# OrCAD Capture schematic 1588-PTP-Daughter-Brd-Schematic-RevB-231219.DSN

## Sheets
1 01_TITLE_BLOCK: title: 01_Title_Block; rev: v2.1
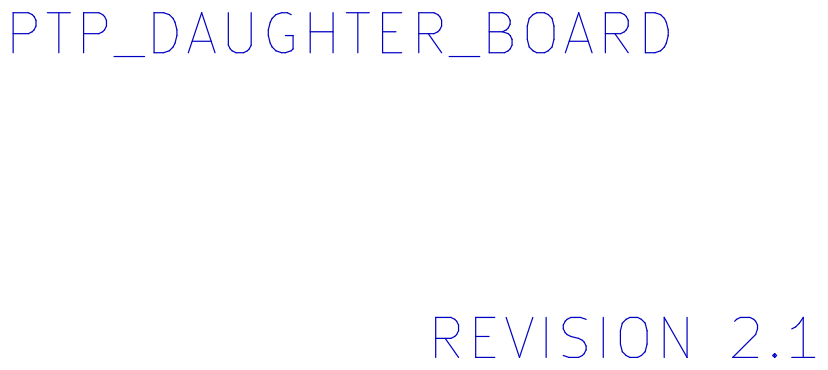
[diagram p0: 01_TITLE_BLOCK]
2 10_FMC_CONNECTOR_2: size A3; title: 10_FMC_CONNECTOR_2
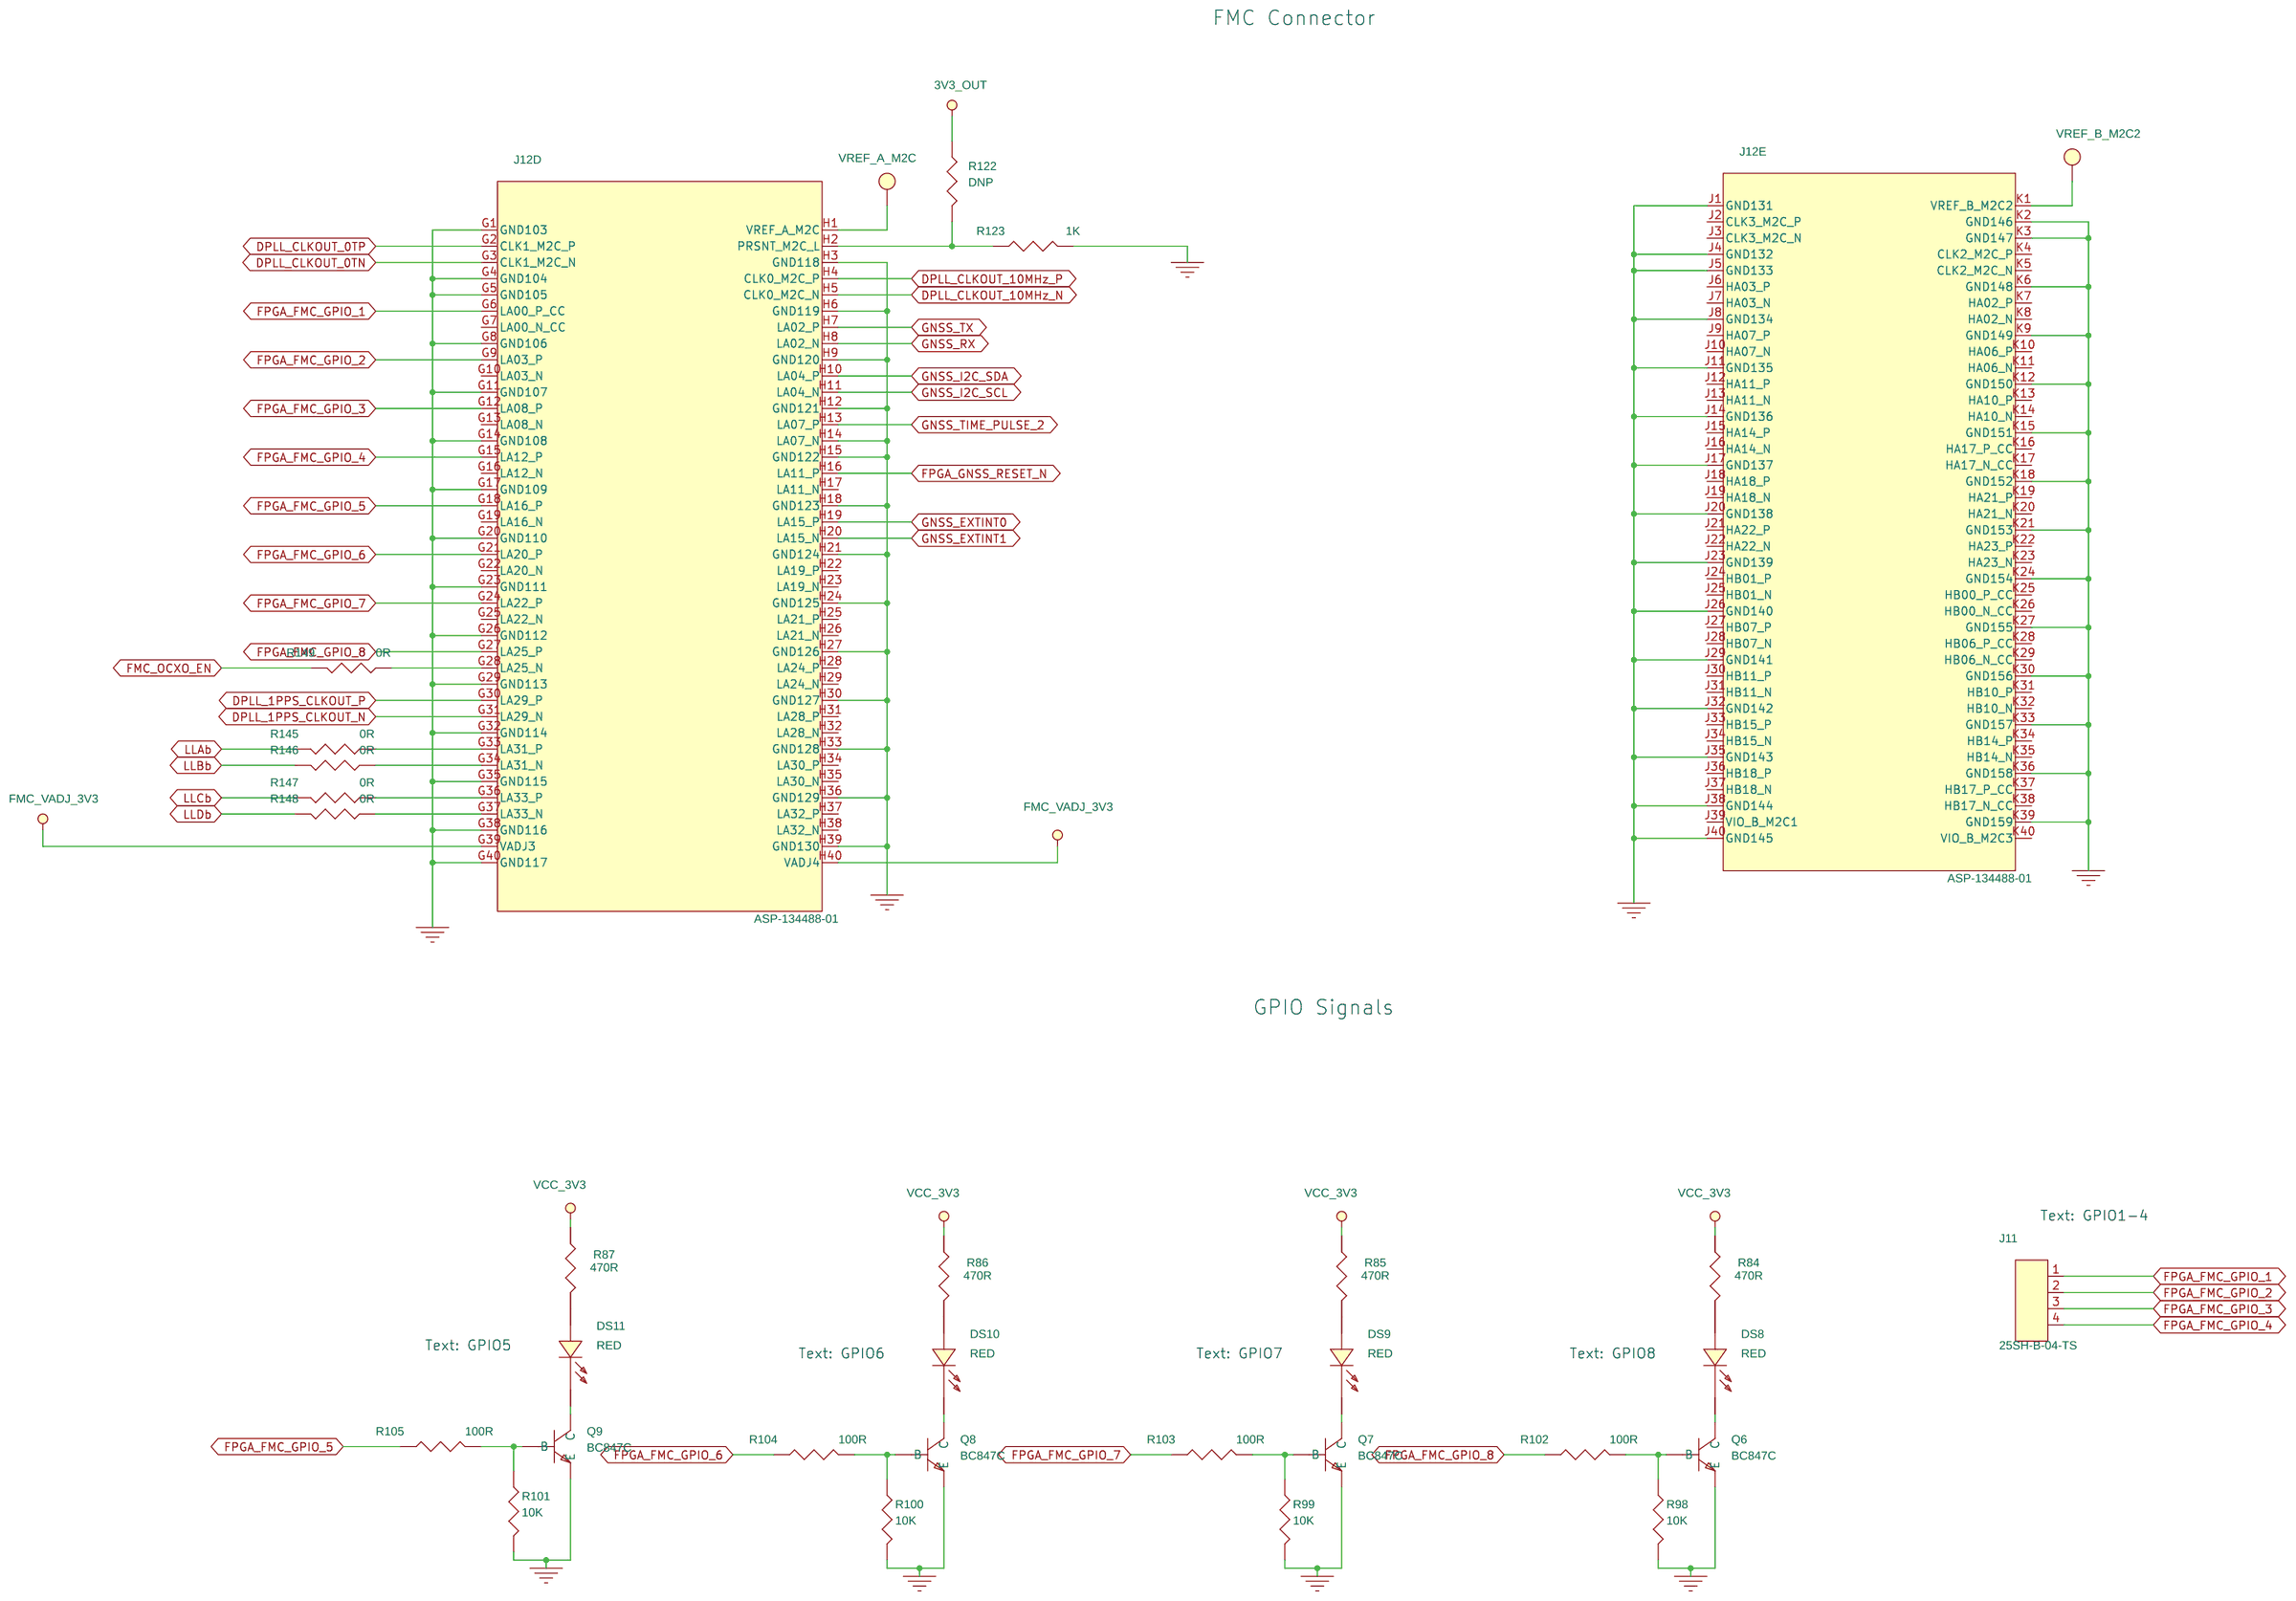
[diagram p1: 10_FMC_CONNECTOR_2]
3 07_OCXO_RJ48: size A3; title: 07_OCXO_RJ48
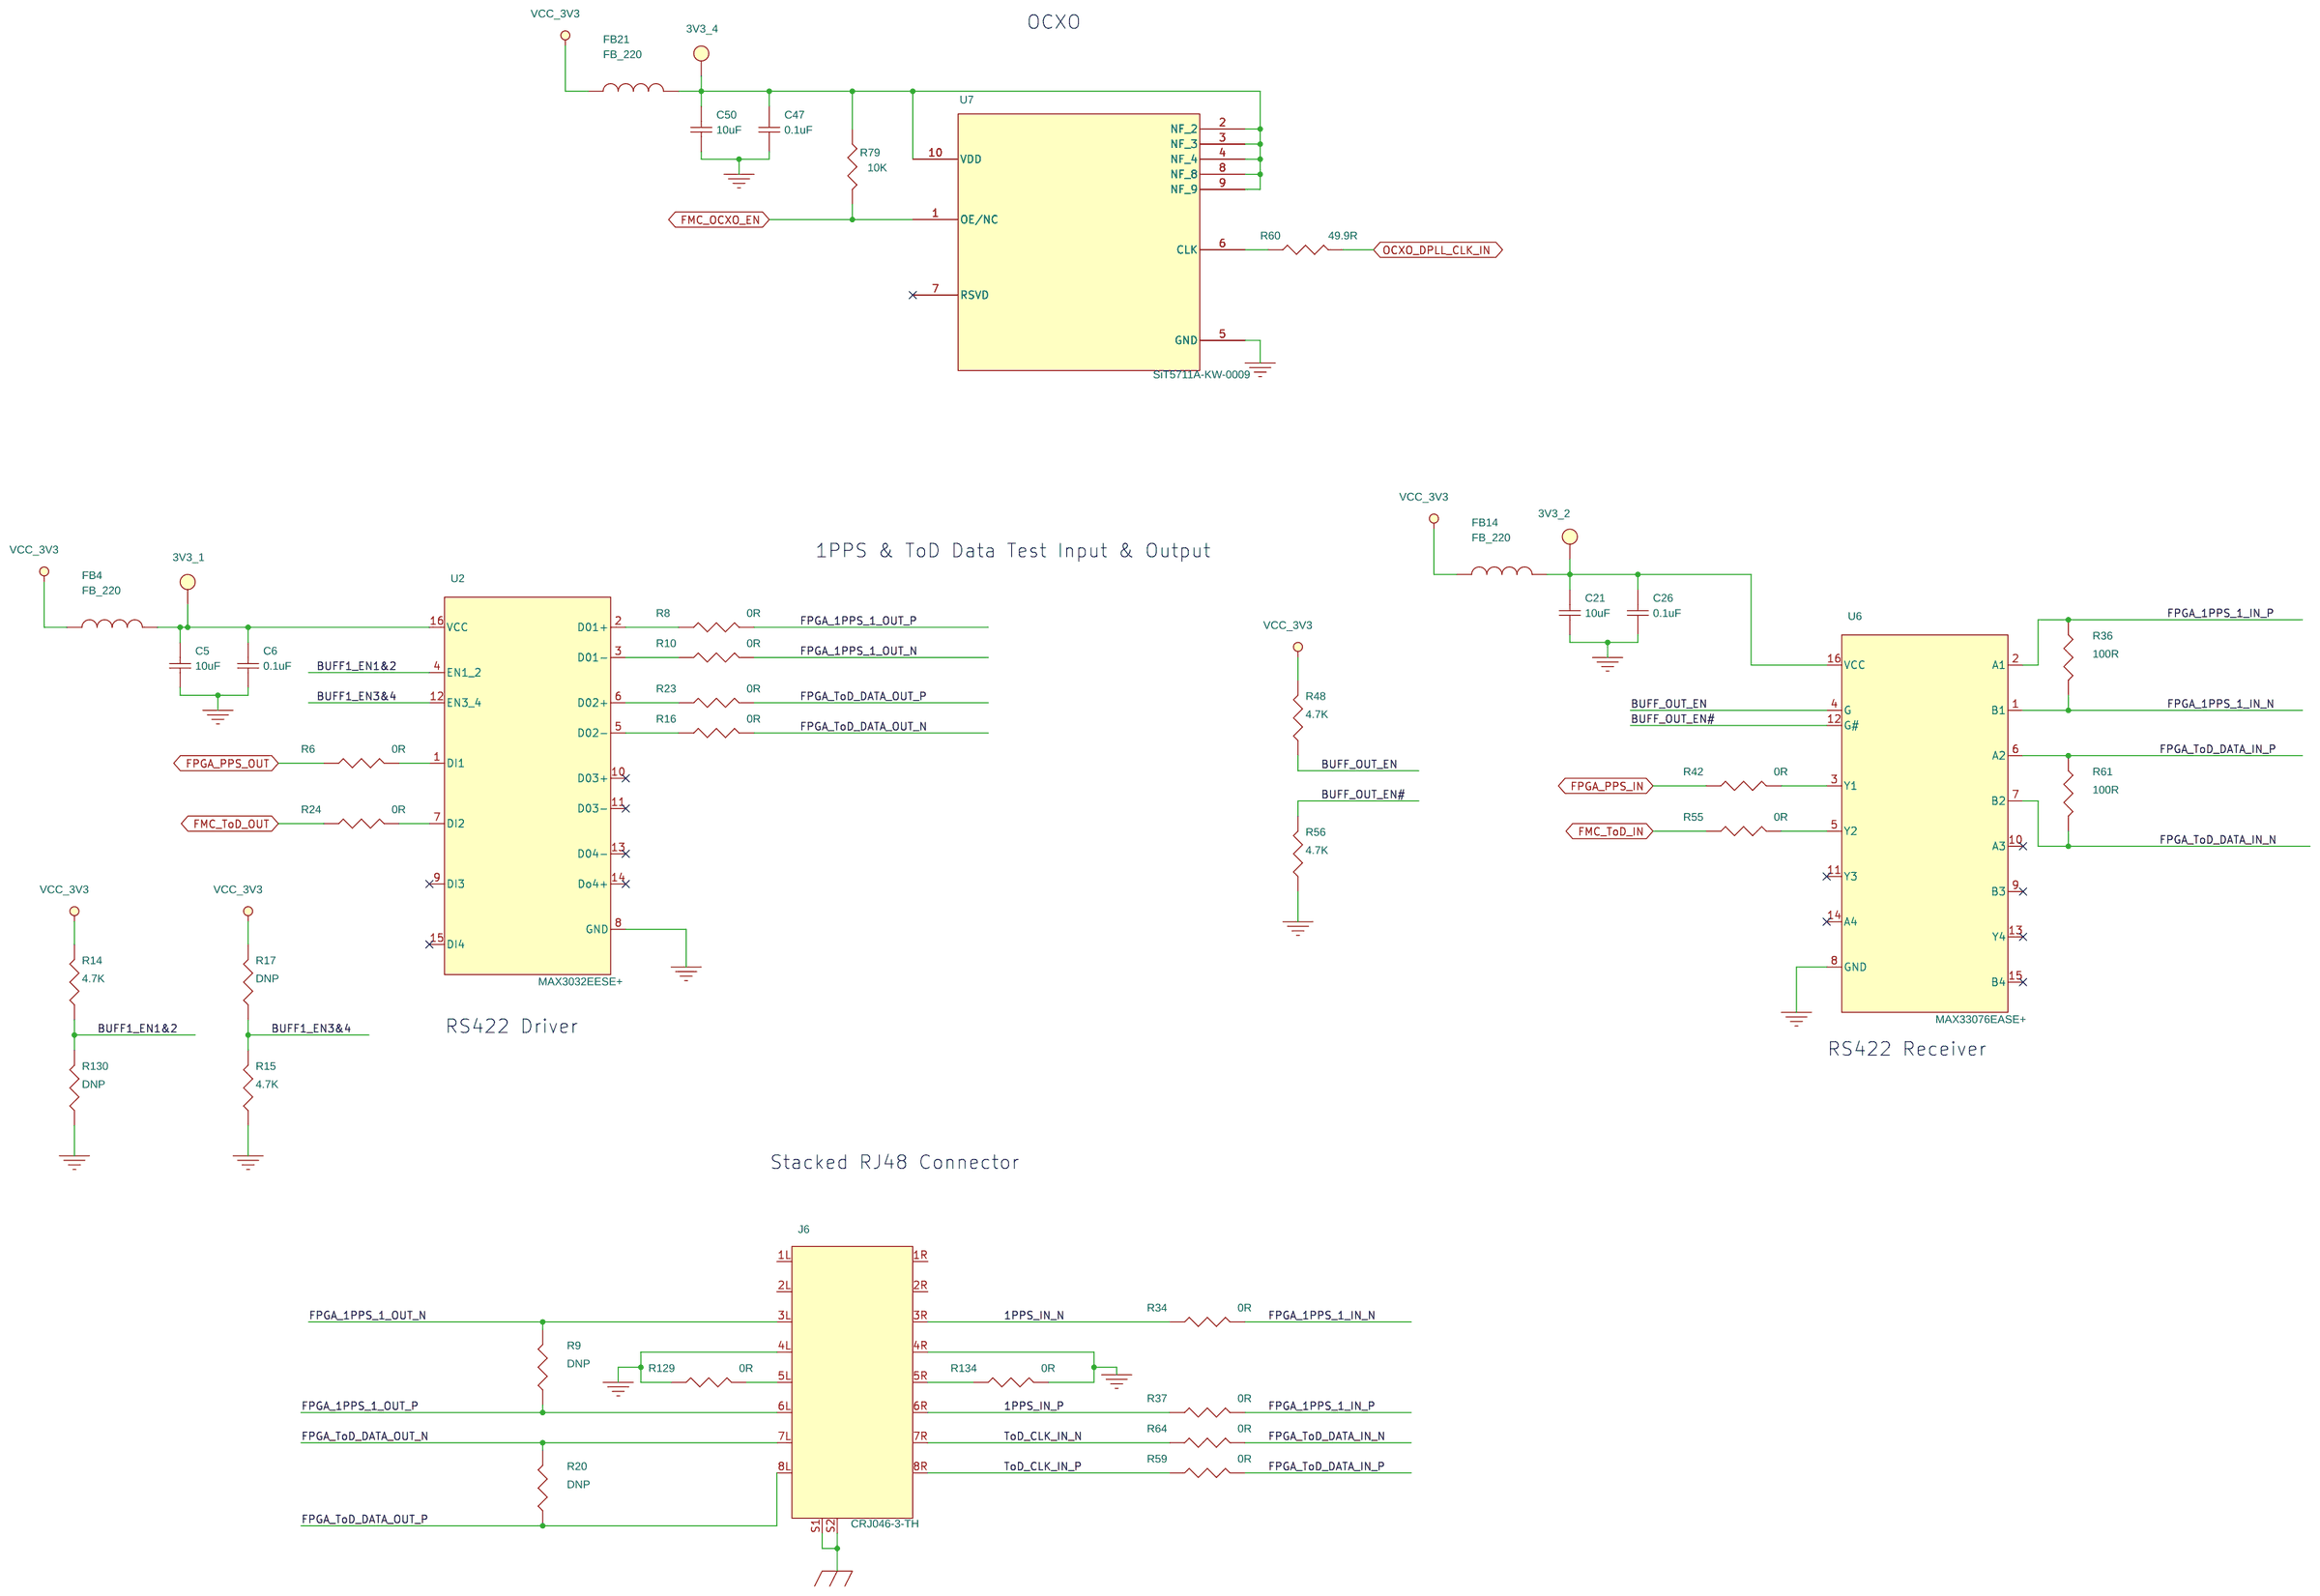
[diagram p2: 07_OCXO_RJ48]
4 09_FMC_CONNECTOR_1: size A3; title: 09_FMC_CONNECTOR_1
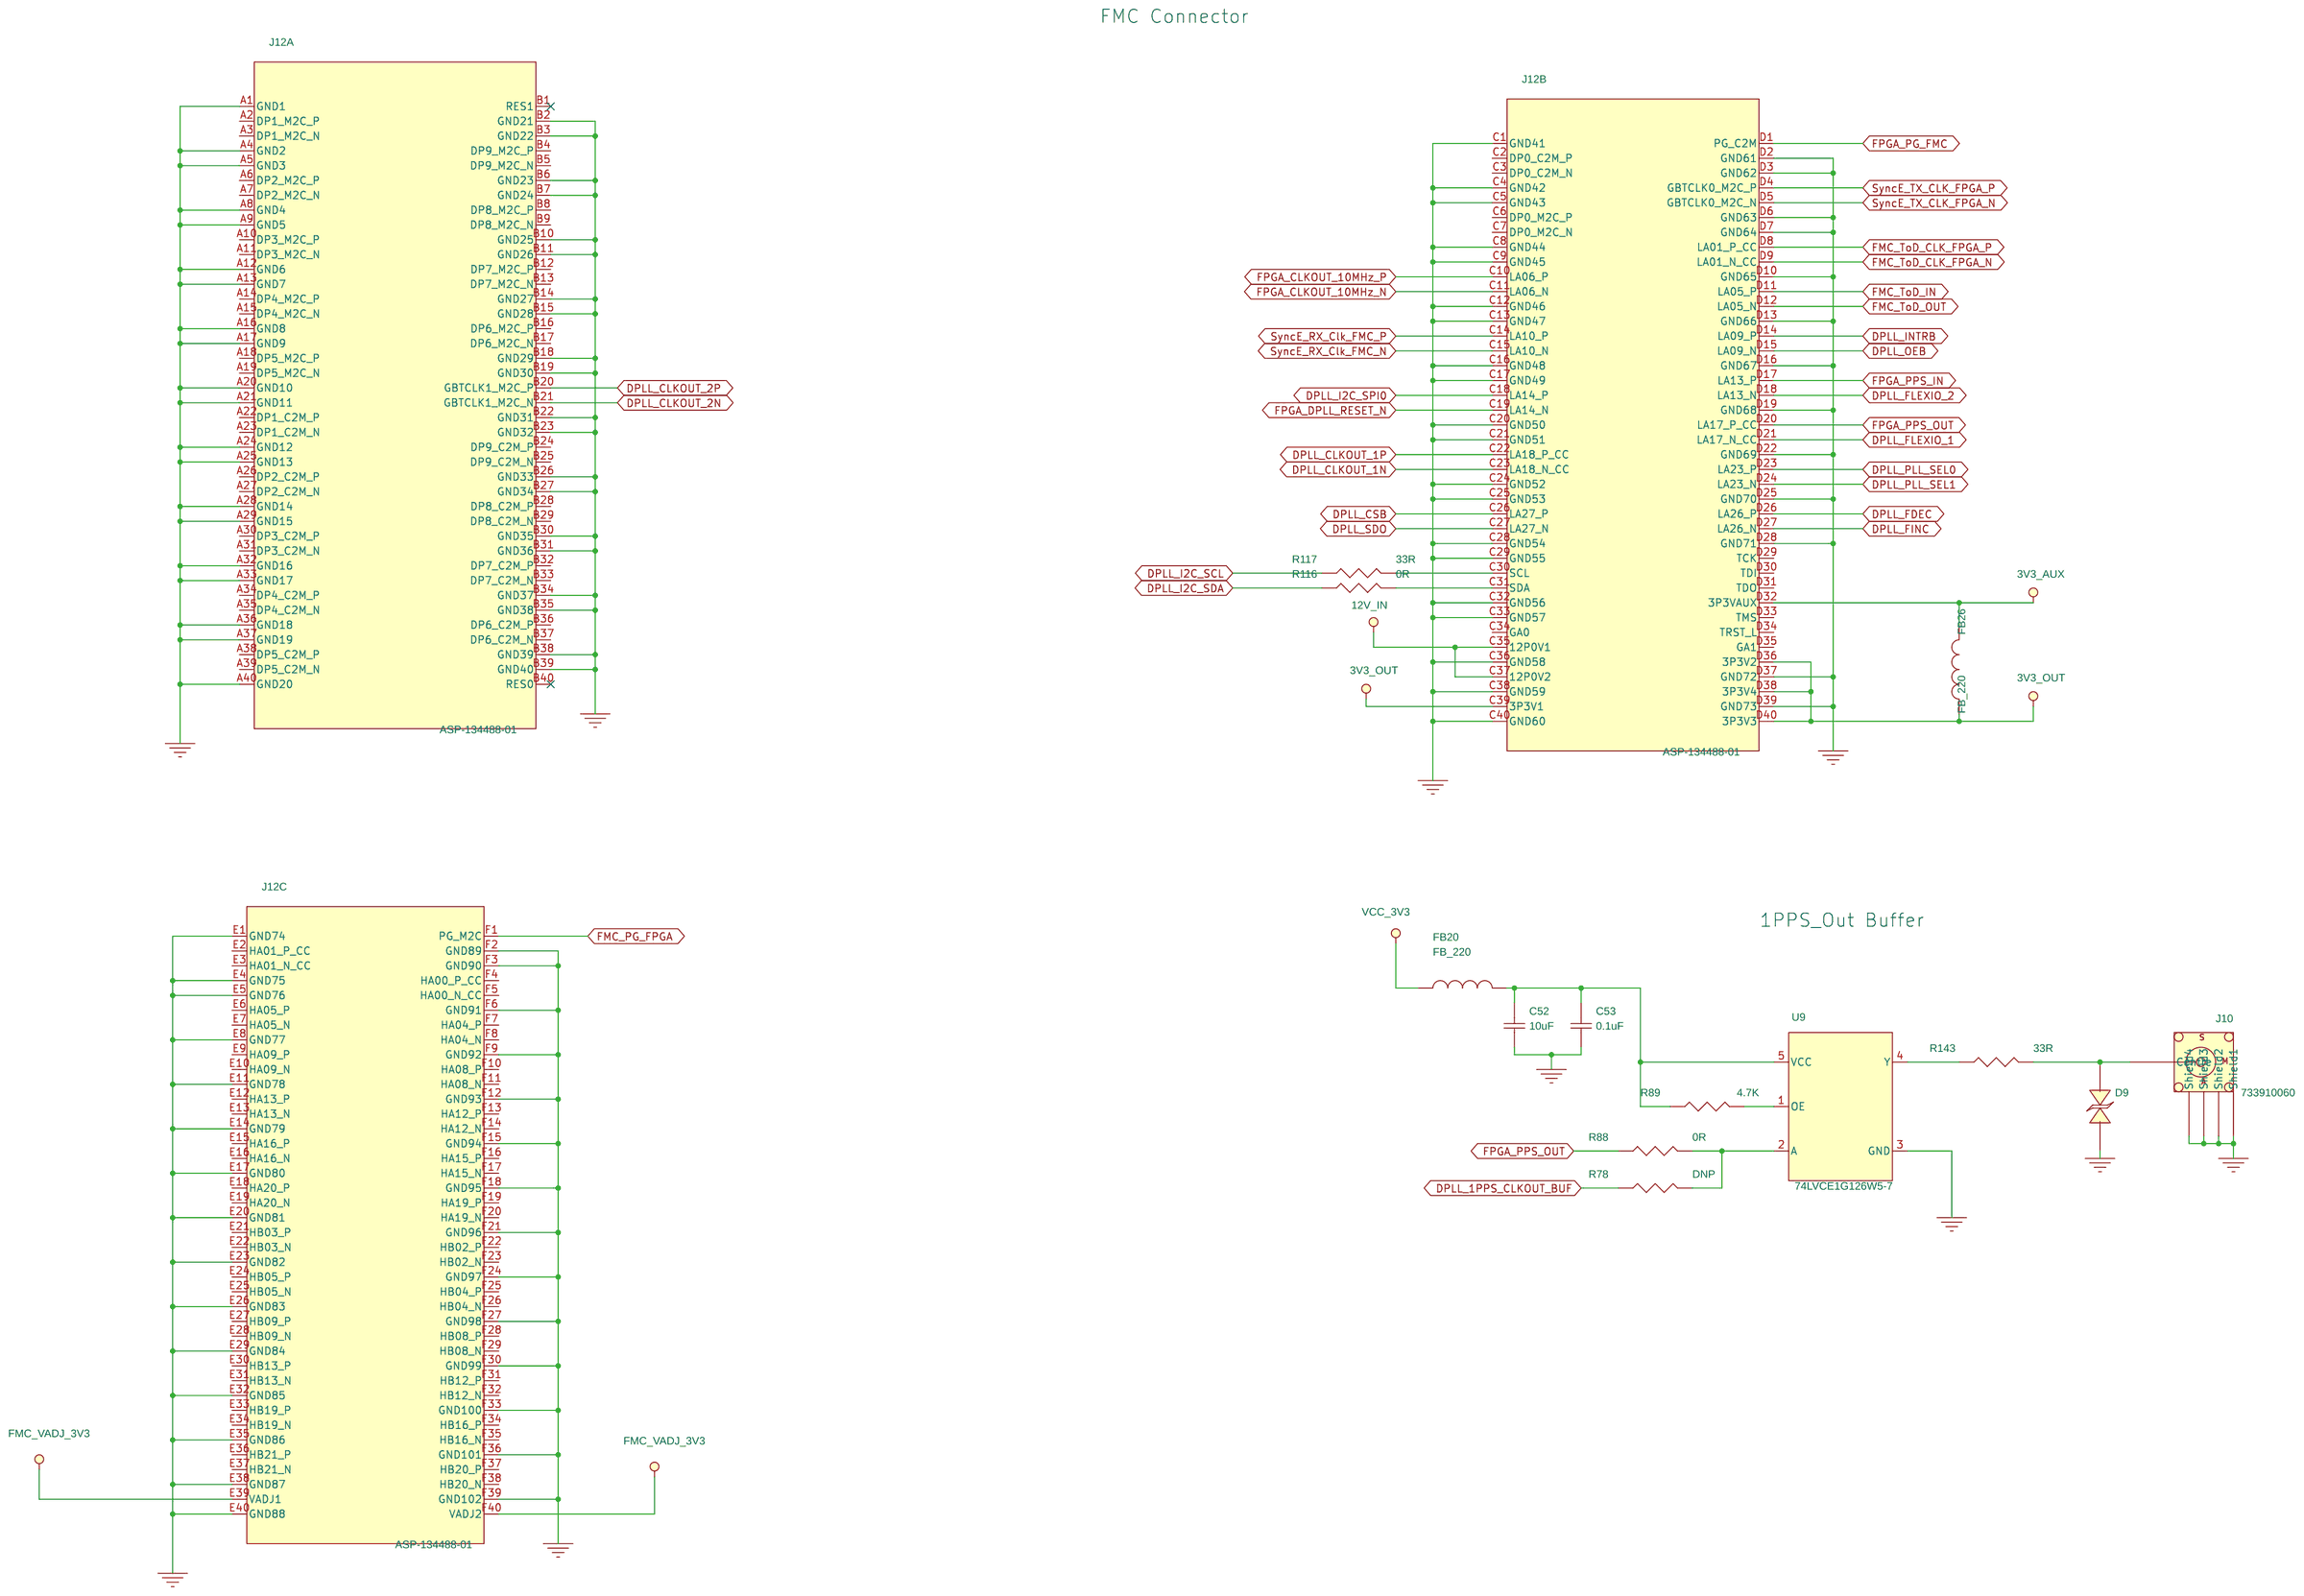
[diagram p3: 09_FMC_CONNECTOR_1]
5 04_POWER_ARCHITECTURE: title: 04_POWER_ARCHITECTURE
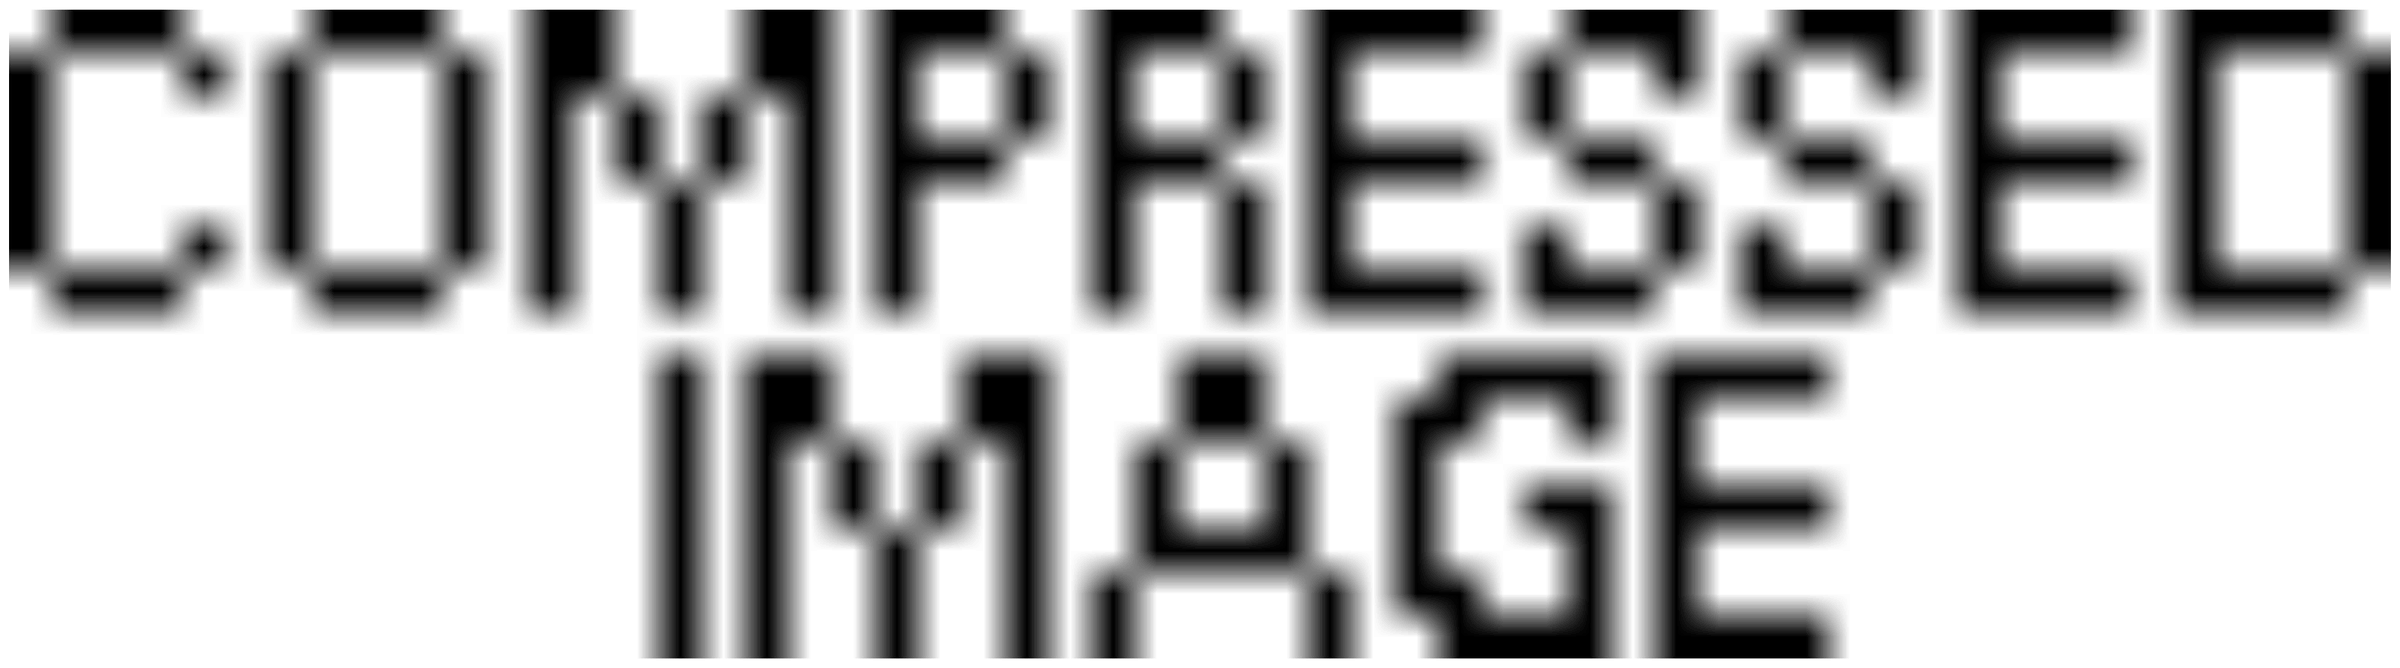
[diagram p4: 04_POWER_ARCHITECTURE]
6 03_BLOCK_DIAGRAM: title: 03_BLOCK_DIAGRAM
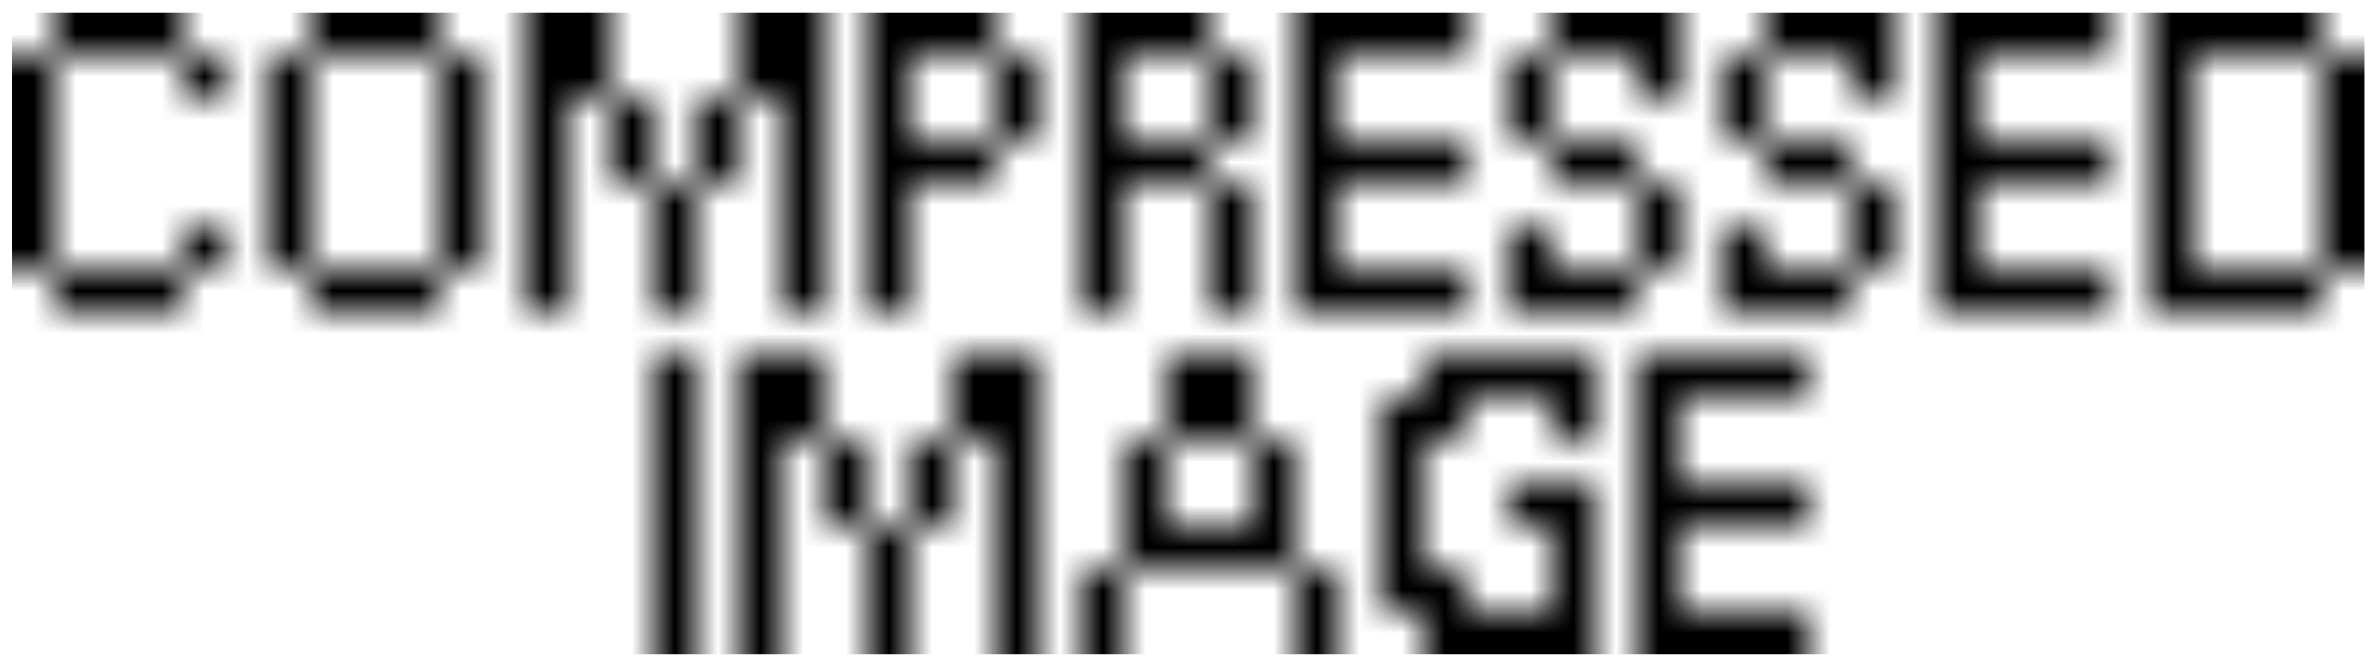
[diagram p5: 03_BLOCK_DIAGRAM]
7 08_POWER_3V3_1V8: size A3; title: 08_POWER_3V3_1V8
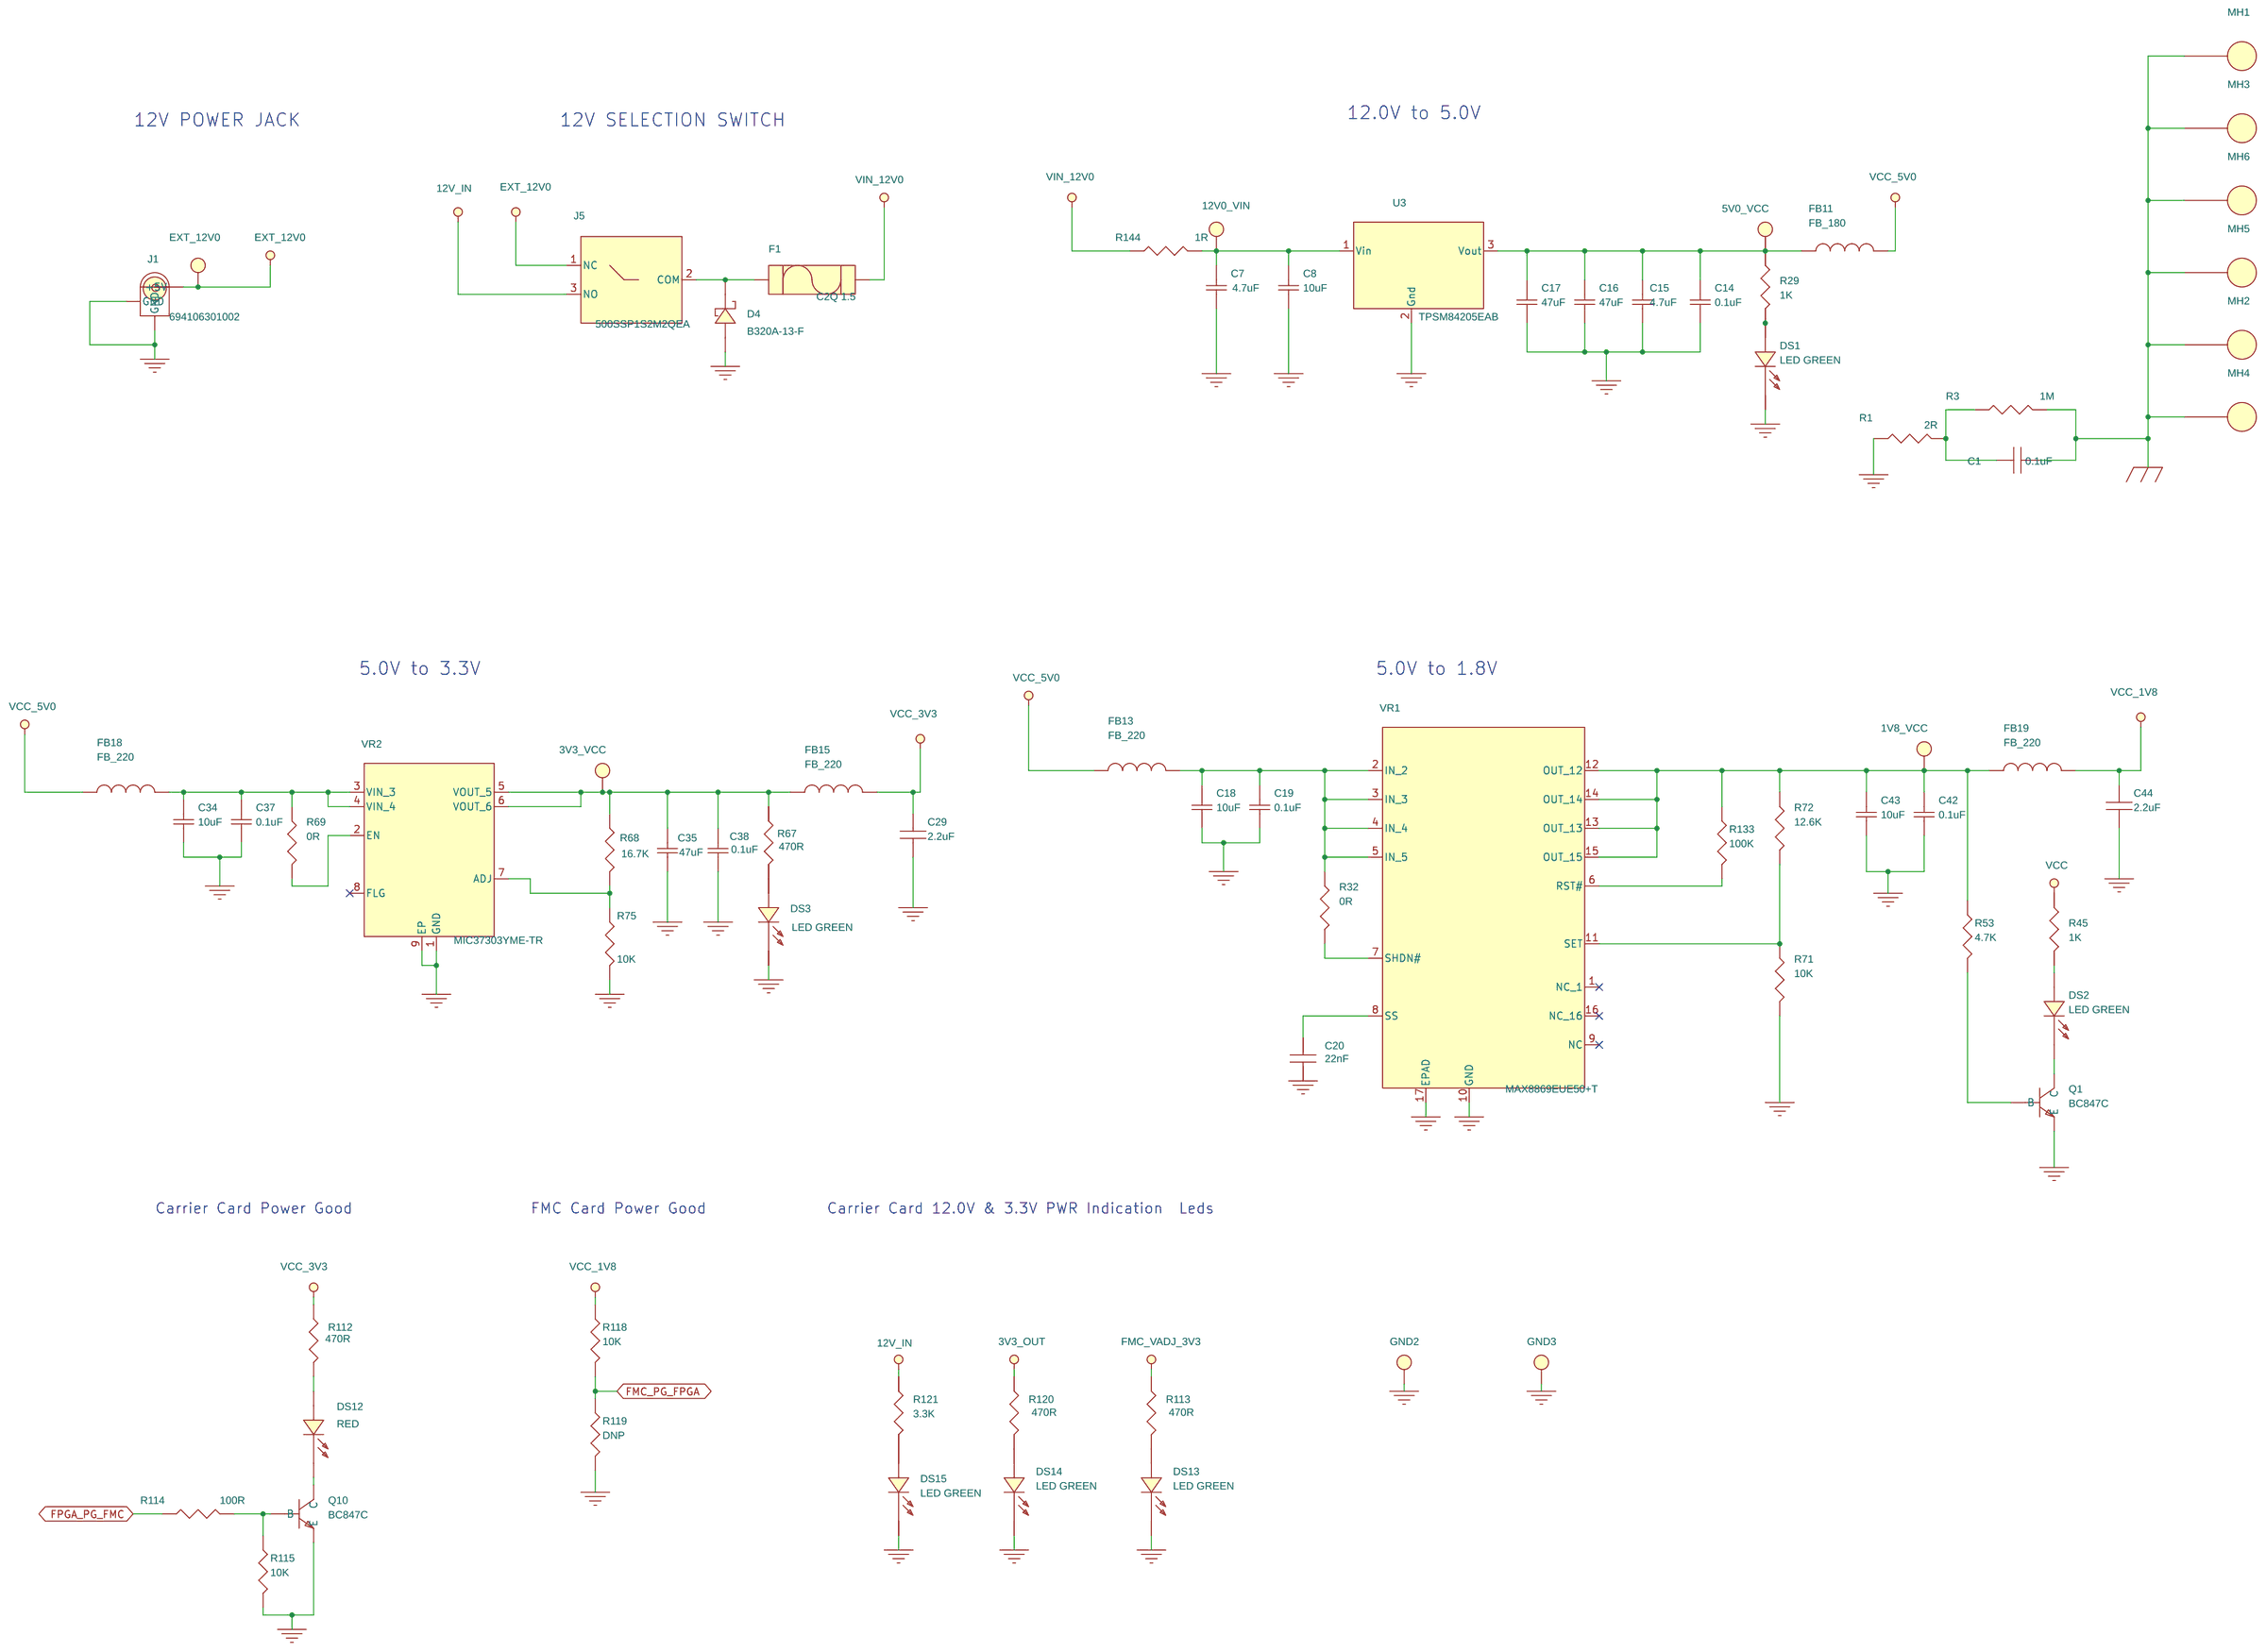
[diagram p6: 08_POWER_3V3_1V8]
8 06_GNSS: size A3; title: 06_GNSS
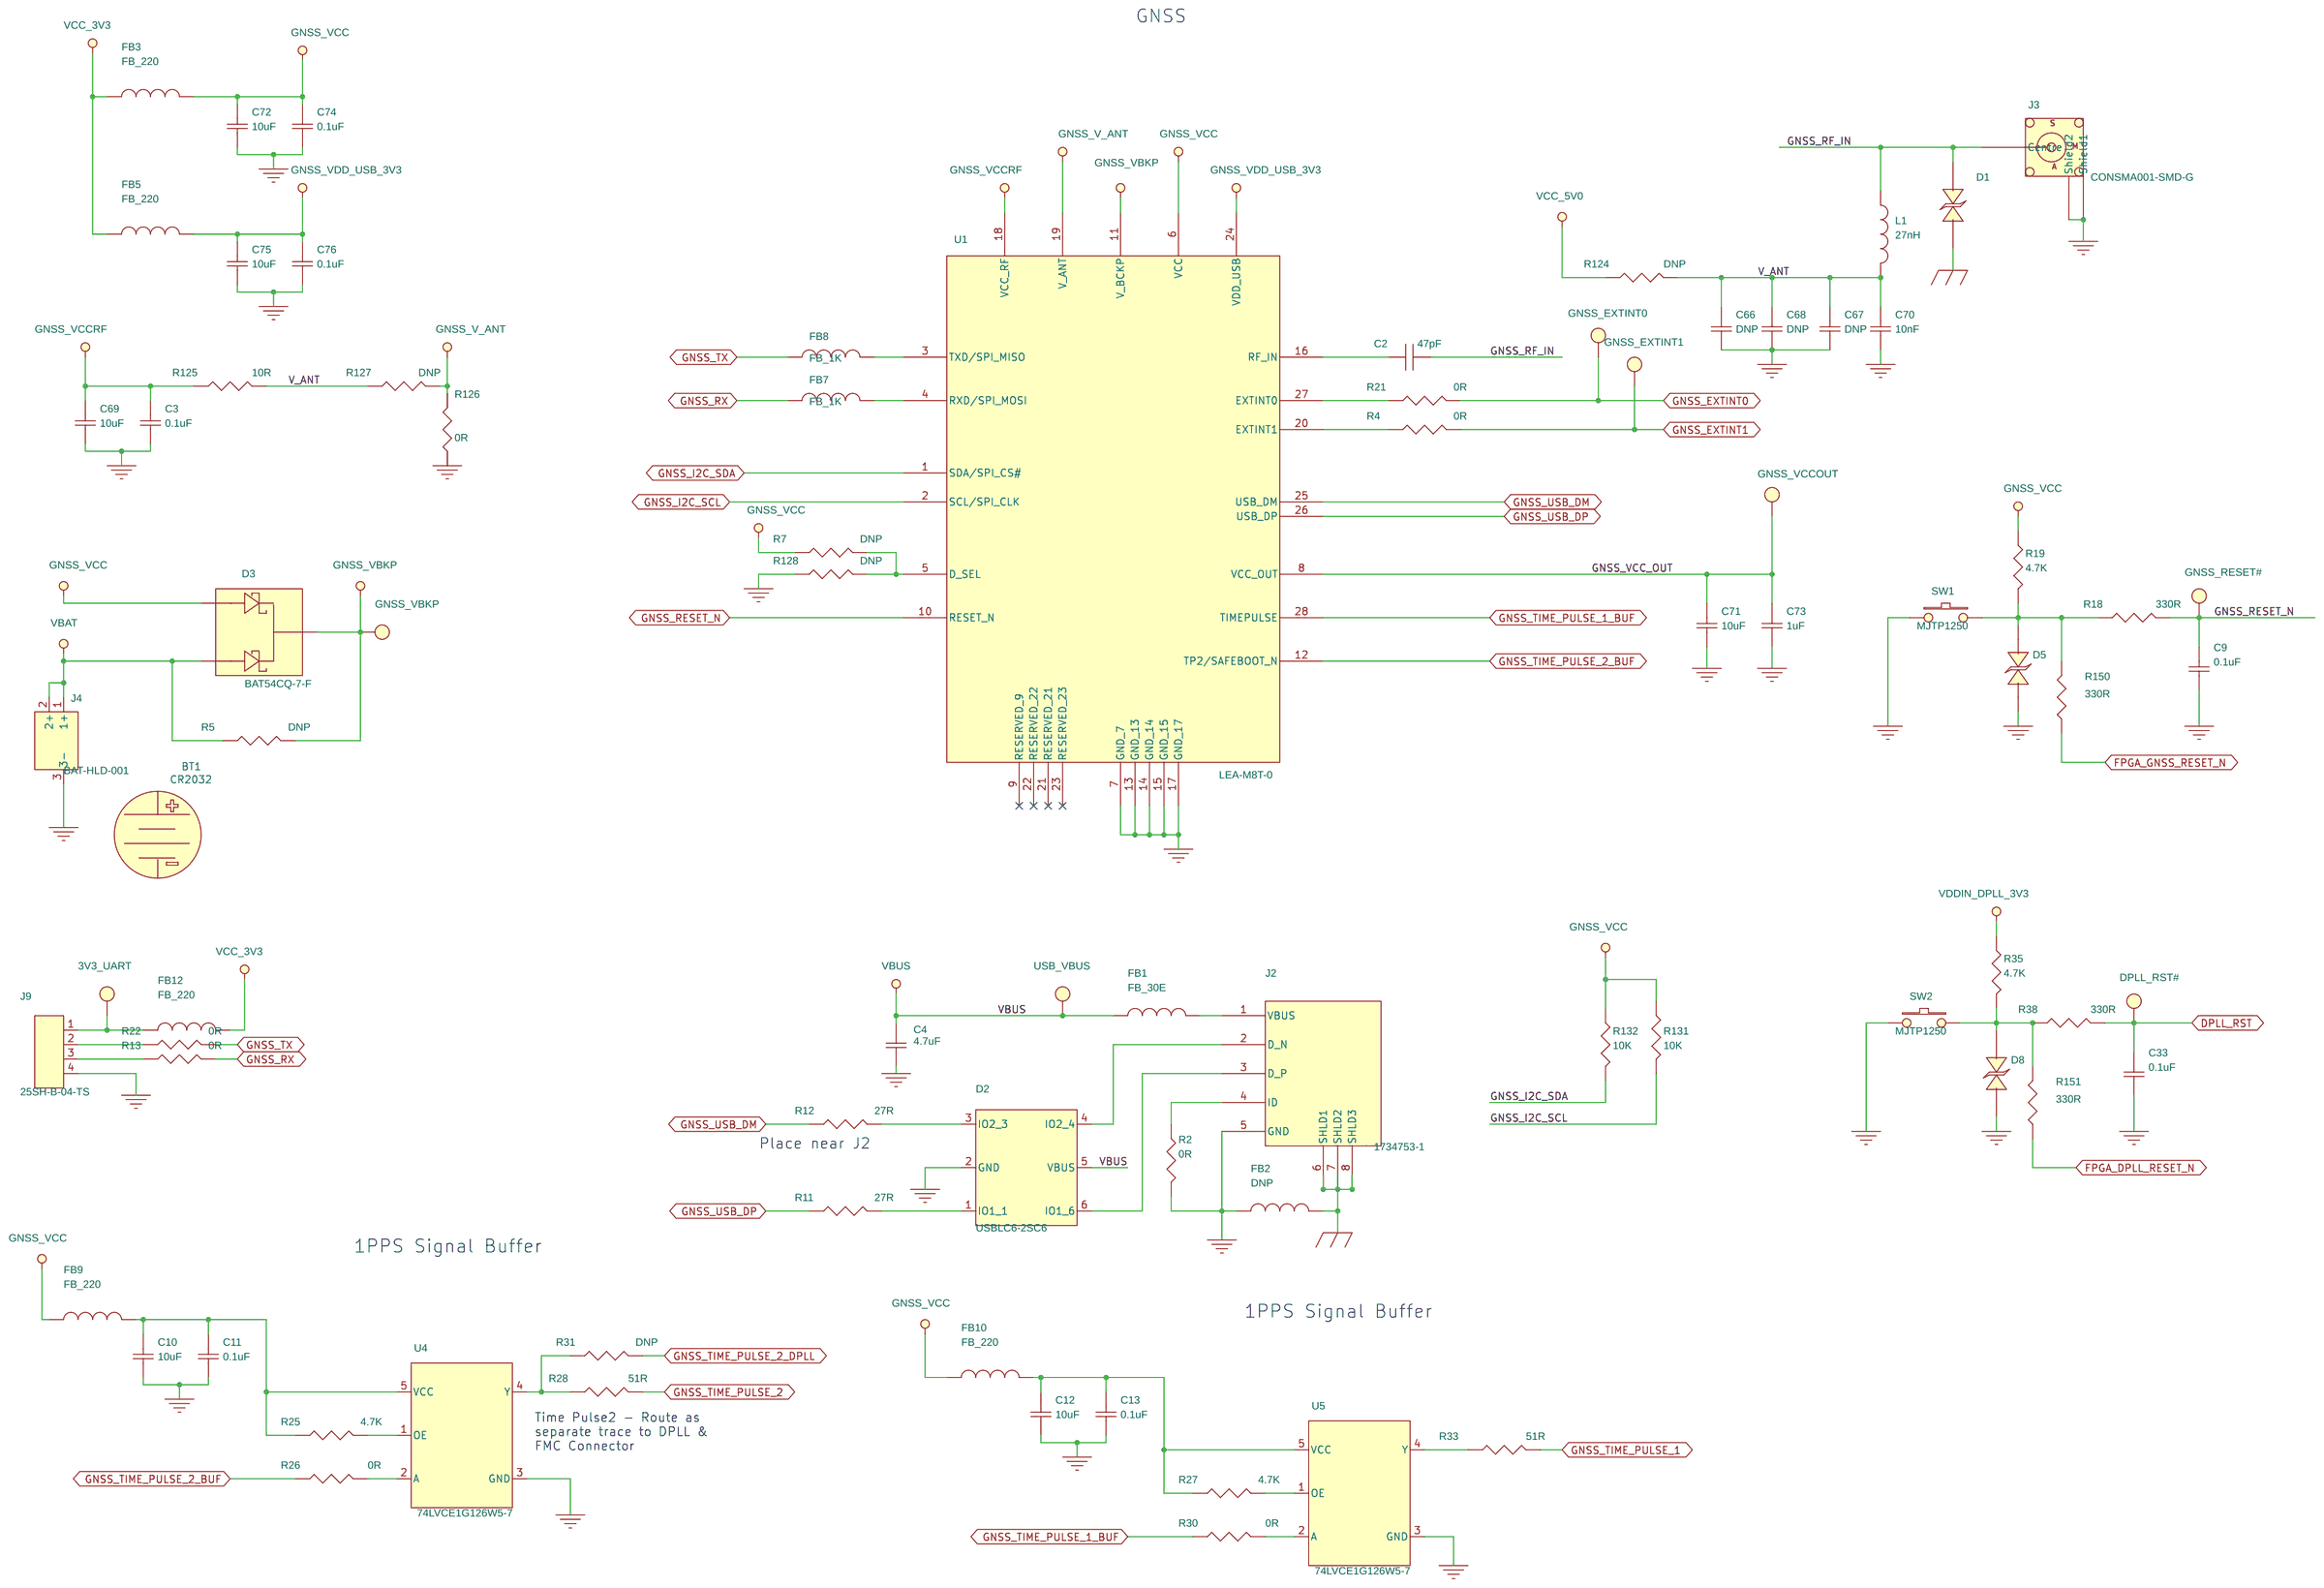
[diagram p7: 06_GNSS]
9 05_DPLL: size A3; title: 05_DPLL
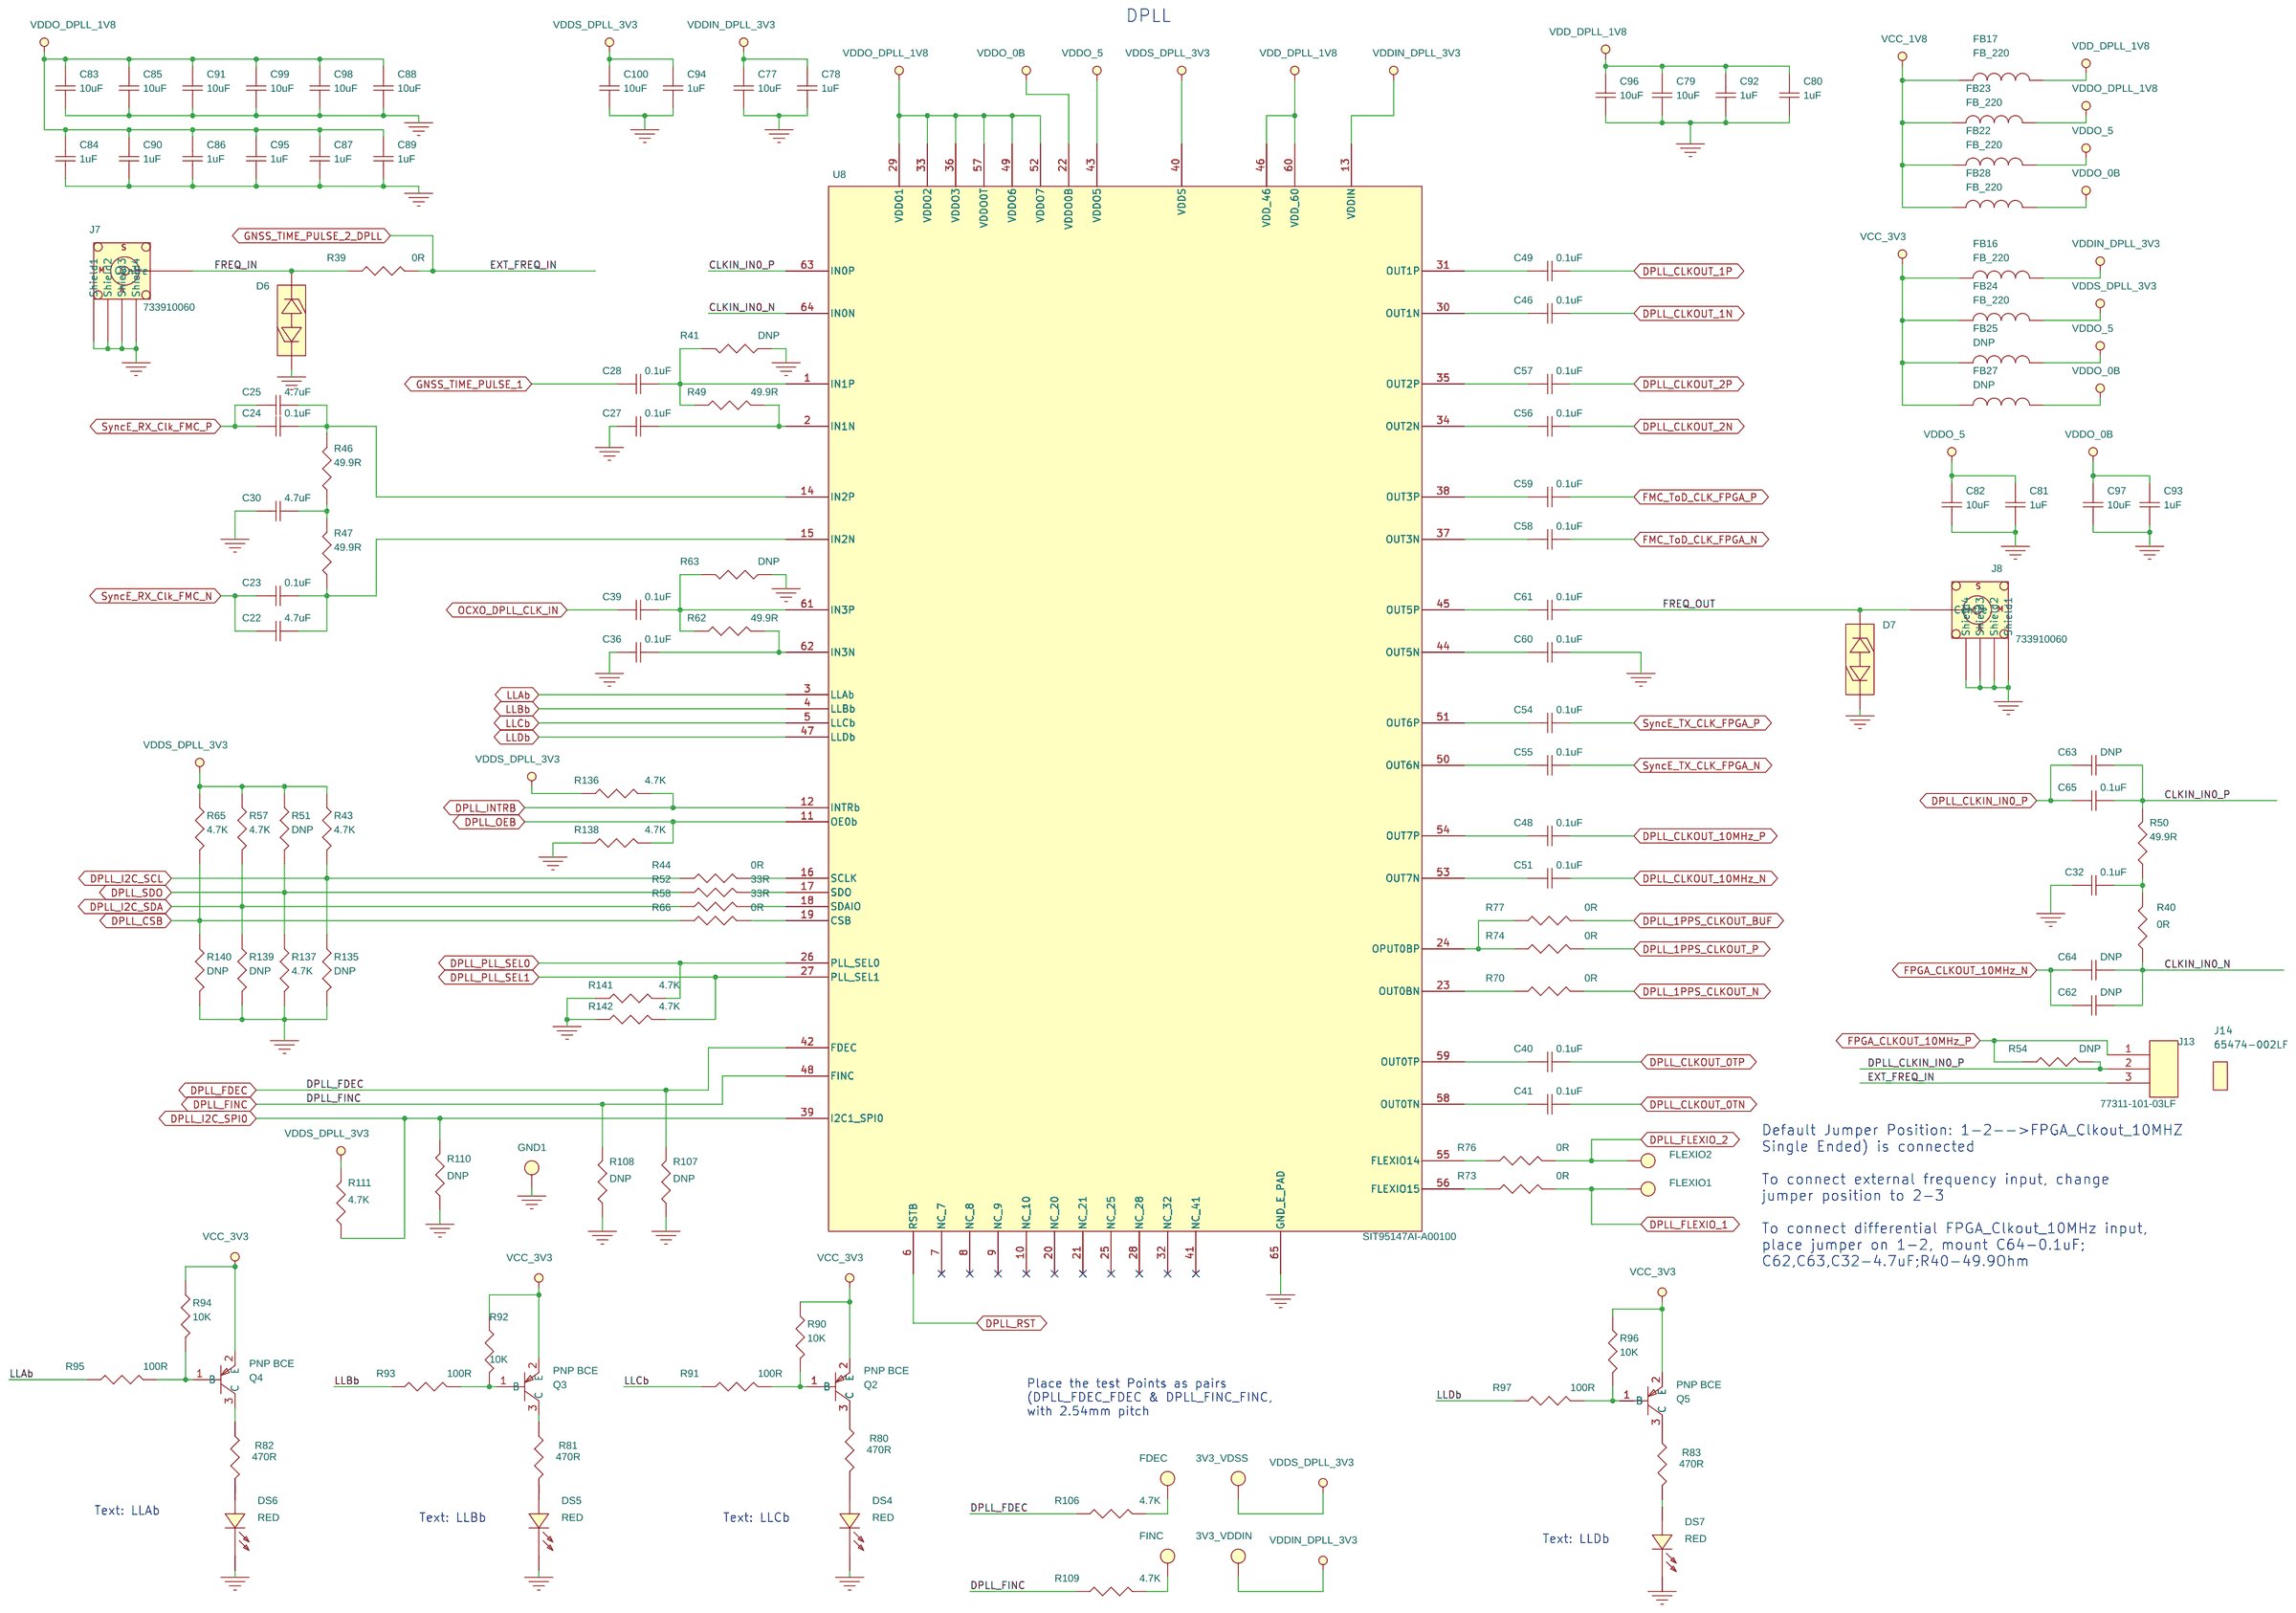
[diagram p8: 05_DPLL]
10 02_INDEX: title: 02_INDEX
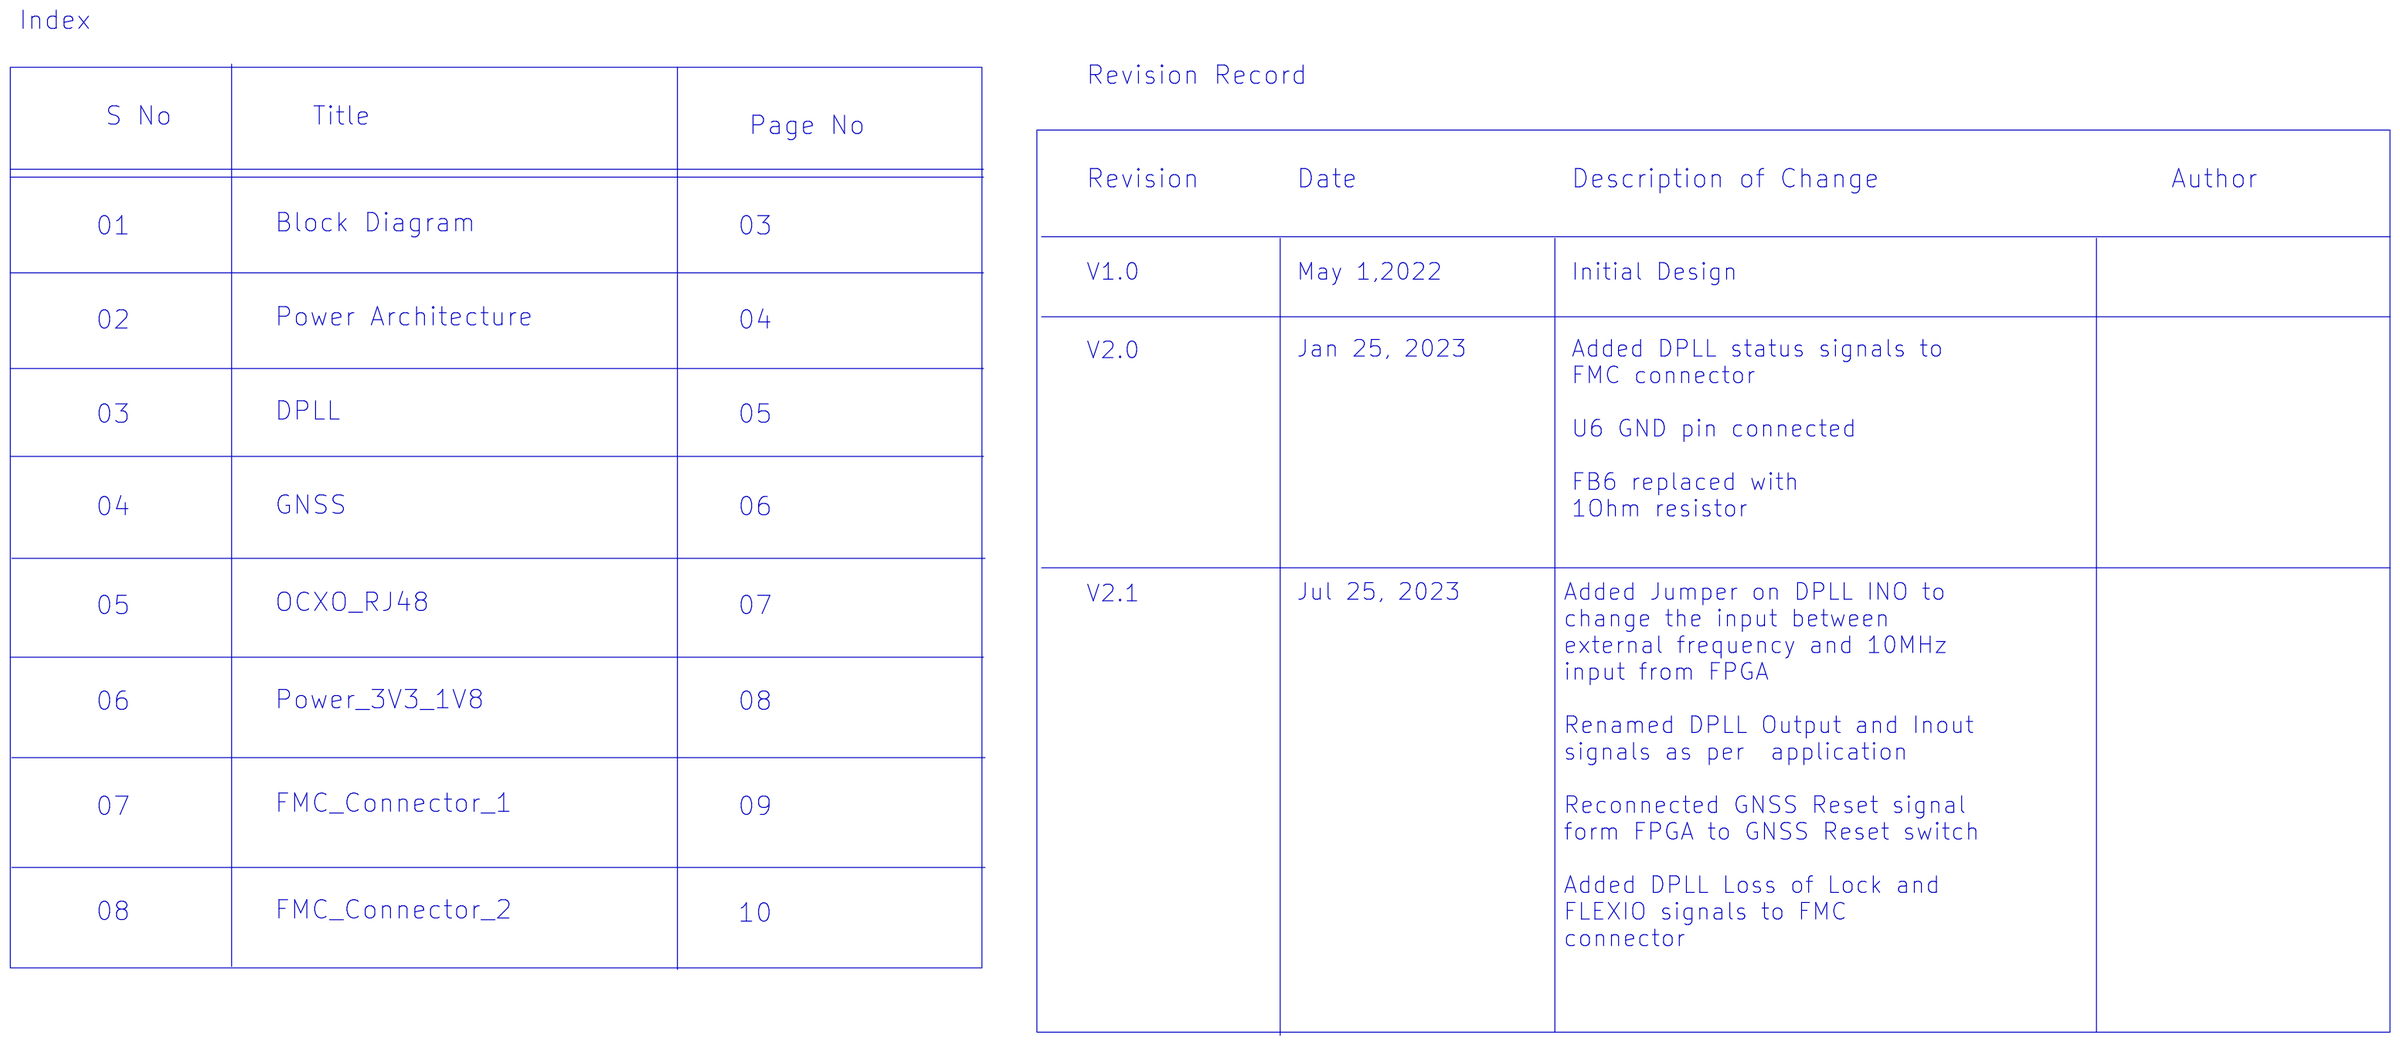
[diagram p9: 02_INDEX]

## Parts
sheet 05_DPLL
3V3_VDDIN  TP  [TP_PTH]
3V3_VDSS  TP  [TP_PTH]
C22  4.7uF  [cap0402]
C23  0.1uF  [cap0402]
C24  0.1uF  [cap0402]
C25  4.7uF  [cap0402]
C27  0.1uF  [cap0402]
C28  0.1uF  [cap0402]
C30  4.7uF  [cap0402]
C32  0.1uF  [cap0402]
C36  0.1uF  [cap0402]
C39  0.1uF  [cap0402]
C40  0.1uF  [cap0402]
C41  0.1uF  [cap0402]
C46  0.1uF  [cap0402]
C48  0.1uF  [cap0402]
C49  0.1uF  [cap0402]
C51  0.1uF  [cap0402]
C54  0.1uF  [cap0402]
C55  0.1uF  [cap0402]
C56  0.1uF  [cap0402]
C57  0.1uF  [cap0402]
C58  0.1uF  [cap0402]
C59  0.1uF  [cap0402]
C60  0.1uF  [cap0402]
C61  0.1uF  [cap0402]
C62  DNP  [cap0402]
C63  DNP  [cap0402]
C64  DNP  [cap0402]
C65  0.1uF  [cap0402]
C77  10uF  [cap0603]
C78  1uF  [cap0402]
C79  10uF  [cap0603]
C80  1uF  [cap0402]
C81  1uF  [cap0402]
C82  10uF  [cap0603]
C83  10uF  [cap0603]
C84  1uF  [cap0402]
C85  10uF  [cap0603]
C86  1uF  [cap0402]
C87  1uF  [cap0402]
C88  10uF  [cap0603]
C89  1uF  [cap0402]
C90  1uF  [cap0402]
C91  10uF  [cap0603]
C92  1uF  [cap0402]
C93  1uF  [cap0402]
C94  1uF  [cap0402]
C95  1uF  [cap0402]
C96  10uF  [cap0603]
C97  10uF  [cap0603]
C98  10uF  [cap0603]
C99  10uF  [cap0603]
C100  10uF  [cap0603]
D6  CPDQC3V3C-HF  [ESD0402]
D7  CPDQC3V3C-HF  [ESD0402]
DS4  RED  [LED0603]
DS5  RED  [LED0603]
DS6  RED  [LED0603]
DS7  RED  [LED0603]
FB16  FB_220  [FB0603]
FB17  FB_220  [FB0603]
FB22  FB_220  [FB0603]
FB23  FB_220  [FB0603]
FB24  FB_220  [FB0603]
FB25  DNP  [FB0603]
FB27  DNP  [FB0603]
FB28  FB_220  [FB0603]
FDEC  TP  [TP_PTH]
FINC  TP  [TP_PTH]
FLEXIO1  TP  [TP_PTH]
FLEXIO2  TP  [TP_PTH]
GND1  TP  [TP_PTH]
J7  733910060  [SMA_JACK_ST]
J8  733910060  [SMA_JACK_ST]
J13  77311-101-03LF  [conn_3pos_2p54_th_st]
J14  65474-002LF  [NA]
Q2  PNP BCE  [SOT23_3]
Q3  PNP BCE  [SOT23_3]
Q4  PNP BCE  [SOT23_3]
Q5  PNP BCE  [SOT23_3]
R39  0R  [res0402]
R40  0R  [res0402]
R41  DNP  [res0402]
R43  4.7K  [res0402]
R44  0R  [res0402]
R46  49.9R  [res0402]
R47  49.9R  [res0402]
R49  49.9R  [res0402]
R50  49.9R  [res0402]
R51  DNP  [res0402]
R52  33R  [res0402]
R54  DNP  [res0402]
R57  4.7K  [res0402]
R58  33R  [res0402]
R62  49.9R  [res0402]
R63  DNP  [res0402]
R65  4.7K  [res0402]
R66  0R  [res0402]
R70  0R  [res0402]
R73  0R  [res0402]
R74  0R  [res0402]
R76  0R  [res0402]
R77  0R  [res0402]
R80  470R  [res0402]
R81  470R  [res0402]
R82  470R  [res0402]
R83  470R  [res0402]
R90  10K  [res0402]
R91  100R  [res0402]
R92  10K  [res0402]
R93  100R  [res0402]
R94  10K  [res0402]
R95  100R  [res0402]
R96  10K  [res0402]
R97  100R  [res0402]
R106  4.7K  [res0402]
R107  DNP  [res0402]
R108  DNP  [res0402]
R109  4.7K  [res0402]
R110  DNP  [res0402]
R111  4.7K  [res0402]
R135  DNP  [res0402]
R136  4.7K  [res0402]
R137  4.7K  [res0402]
R138  4.7K  [res0402]
R139  DNP  [res0402]
R140  DNP  [res0402]
R141  4.7K  [res0402]
R142  4.7K  [res0402]
U8  SIT95147AI-A00100  [QFN_64P_0P5P_EXP_9X9MM]
sheet 06_GNSS
3V3_UART  TP  [TP_PTH]
BT1  CR2032  [NA]
C2  47pF  [cap0402]
C3  0.1uF  [cap0402]
C4  4.7uF  [cap0402]
C9  0.1uF  [cap0402]
C10  10uF  [cap0603]
C11  0.1uF  [cap0402]
C12  10uF  [cap0603]
C13  0.1uF  [cap0402]
C33  0.1uF  [cap0402]
C66  DNP  [cap0603]
C67  DNP  [cap0402]
C68  DNP  [cap0402]
C69  10uF  [cap0603]
C70  10nF  [cap0603]
C71  10uF  [cap0603]
C72  10uF  [cap0603]
C73  1uF  [cap0603]
C74  0.1uF  [cap0402]
C75  10uF  [cap0603]
C76  0.1uF  [cap0402]
D1  PESD0402-140  [ESD0402]
D2  USBLC6-2SC6  [SOT-23_6PIN]
D3  BAT54CQ-7-F  [sot23_3]
D5  DESD3V3E1BL-7B  [ESD0402]
D8  DESD3V3E1BL-7B  [ESD0402]
DPLL_RST#  TP  [TP_50]
FB1  FB_30E  [FB0603]
FB2  DNP  [FB0402]
FB3  FB_220  [FB0603]
FB5  FB_220  [FB0603]
FB7  FB_1K  [FB0402]
FB8  FB_1K  [FB0402]
FB9  FB_220  [FB0603]
FB10  FB_220  [FB0603]
FB12  FB_220  [FB0603]
GNSS_EXTINT0  TP  [TP_50]
GNSS_EXTINT1  TP  [TP_50]
GNSS_RESET#  TP  [TP_50]
GNSS_VBKP  TP  [TP_50]
GNSS_VCCOUT  TP  [TP_PTH]
J2  1734753-1  [usb_rcpt_btype]
J3  CONSMA001-SMD-G  [SMA_RCPT_SMD]
J4  BAT-HLD-001  [BATT_HLDR_SMD_23MM]
J9  25SH-B-04-TS  [CON_4POS_2P5P_ST_TH]
L1  27nH  [FB0402]
R2  0R  [res0402]
R4  0R  [res0603]
R5  DNP  [res0603]
R7  DNP  [res0603]
R11  27R  [res0402]
R12  27R  [res0402]
R13  0R  [res0603]
R18  330R  [res0402]
R19  4.7K  [RES0402]
R21  0R  [res0603]
R22  0R  [res0603]
R25  4.7K  [res0402]
R26  0R  [res0402]
R27  4.7K  [res0402]
R28  51R  [res0402]
R30  0R  [res0402]
R31  DNP  [res0402]
R33  51R  [res0402]
R35  4.7K  [RES0402]
R38  330R  [res0402]
R124  DNP  [res0603]
R125  10R  [res0603]
R126  0R  [res0603]
R127  DNP  [res0603]
R128  DNP  [res0603]
R131  10K  [res0402]
R132  10K  [res0402]
R150  330R  [res0402]
R151  330R  [res0402]
SW1  MJTP1250  [SW_MJTP1250]
SW2  MJTP1250  [SW_MJTP1250]
U1  LEA-M8T-0  [MODULE_LEA-M8T-0]
U4  74LVCE1G126W5-7  [SOT23-5]
U5  74LVCE1G126W5-7  [SOT23-5]
USB_VBUS  TP  [TP_PTH]
sheet 07_OCXO_RJ48
3V3_1  TP  [TP_50]
3V3_2  TP  [TP_50]
3V3_4  TP  [TP_50]
C5  10uF  [cap0603]
C6  0.1uF  [cap0402]
C21  10uF  [cap0603]
C26  0.1uF  [cap0402]
C47  0.1uF  [cap0402]
C50  10uF  [cap0603]
FB4  FB_220  [FB0603]
FB14  FB_220  [FB0603]
FB21  FB_220  [FB0603]
J6  CRJ046-3-TH  [RJ45_DUALPORT_CRJ046-3-TH]
R6  0R  [res0402]
R8  0R  [res0402]
R9  DNP  [res0402]
R10  0R  [res0402]
R14  4.7K  [res0402]
R15  4.7K  [res0402]
R16  0R  [res0402]
R17  DNP  [res0402]
R20  DNP  [res0402]
R23  0R  [res0402]
R24  0R  [res0402]
R34  0R  [res0402]
R36  100R  [res0402]
R37  0R  [res0402]
R42  0R  [res0402]
R48  4.7K  [res0402]
R55  0R  [res0402]
R56  4.7K  [res0402]
R59  0R  [res0402]
R60  49.9R  [res0402]
R61  100R  [res0402]
R64  0R  [res0402]
R79  10K  [res0402]
R129  0R  [res0402]
R130  DNP  [res0402]
R134  0R  [res0402]
U2  MAX3032EESE+  [SO16_50_157X393]
U6  MAX33076EASE+  [SO16_50_157X393]
U7  SiT5711A-KW-0009  [XTAL_10P_9X7MM]
sheet 08_POWER_3V3_1V8
1V8_VCC  TP  [TP_50]
3V3_VCC  TP  [TP_50]
5V0_VCC  TP  [TP_50]
12V0_VIN  TP  [TP_50]
C1  0.1uF  [cap1210]
C7  4.7uF  [cap0603]
C8  10uF  [cap0805]
C14  0.1uF  [cap0402]
C15  4.7uF  [cap0603]
C16  47uF  [cap0805]
C17  47uF  [cap0805]
C18  10uF  [cap0603]
C19  0.1uF  [cap0402]
C20  22nF  [cap0402]
C29  2.2uF  [CAP0402]
C34  10uF  [cap0603]
C35  47uF  [cap0805]
C37  0.1uF  [cap0402]
C38  0.1uF  [cap0402]
C42  0.1uF  [cap0402]
C43  10uF  [cap0603]
C44  2.2uF  [CAP0402]
D4  B320A-13-F  [diode_sma]
DS1  LED GREEN  [LED0603]
DS2  LED GREEN  [LED0603]
DS3  LED GREEN  [LED0603]
DS12  RED  [LED0603]
DS13  LED GREEN  [LED0603]
DS14  LED GREEN  [LED0603]
DS15  LED GREEN  [LED0603]
EXT_12V0  TP  [TP_PTH]
F1  C2Q 1.5  [fuse0603]
FB11  FB_180  [FB0805]
FB13  FB_220  [FB0603]
FB15  FB_220  [FB0603]
FB18  FB_220  [FB0603]
FB19  FB_220  [FB0603]
GND2  TP  [TP_PTH]
GND3  TP  [TP_PTH]
J1  694106301002  [694106301002]
J5  500SSP1S2M2QEA  [spdt_3_1p0_4p70]
MH1  M_HOLE  [MH_3P2D_5P0_PTH]
MH2  M_HOLE  [MH_3P2D_5P0_PTH]
MH3  M_HOLE  [MH_3P2D_5P0_PTH]
MH4  M_HOLE  [MH_3P2D_5P0_PTH]
MH5  M_HOLE  [MH_3P2D_5P0_PTH]
MH6  M_HOLE  [MH_3P2D_5P0_PTH]
Q1  BC847C  [sot23_3]
Q10  BC847C  [sot23_3]
R1  2R  [res0805]
R3  1M  [res0805]
R29  1K  [res0402]
R32  0R  [res0603]
R45  1K  [res0402]
R53  4.7K  [res0402]
R67  470R  [res0402]
R68  16.7K  [res0603]
R69  0R  [res0603]
R71  10K  [res0603]
R72  12.6K  [res0603]
R75  10K  [res0603]
R112  470R  [res0402]
R113  470R  [res0402]
R114  100R  [res0402]
R115  10K  [res0402]
R118  10K  [res0402]
R119  DNP  [res0402]
R120  470R  [res0402]
R121  3.3K  [res0402]
R133  100K  [res0402]
R144  1R  [res1206]
U3  TPSM84205EAB  [SIP_3P_11X7P8MM_TH]
VR1  MAX8869EUE50+T  [TSSOP_16P_EXP_0P65P_6P5X5P1MM]
VR2  MIC37303YME-TR  [SOIC_8_160MIL_EXP]
sheet 09_FMC_CONNECTOR_1
C52  10uF  [cap0603]
C53  0.1uF  [cap0402]
D9  DESD3V3E1BL-7B  [ESD0402]
FB20  FB_220  [FB0603]
FB26  FB_220  [FB0603]
J10  733910060  [SMA_JACK_ST]
R78  DNP  [res0402]
R88  0R  [res0402]
R89  4.7K  [res0402]
R116  0R  [res0402]
R117  33R  [res0402]
R143  33R  [res0402]
U9  74LVCE1G126W5-7  [SOT23-5]
sheet 10_FMC_CONNECTOR_2
DS8  RED  [LED0603]
DS9  RED  [LED0603]
DS10  RED  [LED0603]
DS11  RED  [LED0603]
J11  25SH-B-04-TS  [CON_4POS_2P5P_ST_TH]
J12  ASP-134488-01  [ASP-134488-01]  (sections A,B,C,D,E)
Q6  BC847C  [sot23_3]
Q7  BC847C  [sot23_3]
Q8  BC847C  [sot23_3]
Q9  BC847C  [sot23_3]
R84  470R  [res0402]
R85  470R  [res0402]
R86  470R  [res0402]
R87  470R  [res0402]
R98  10K  [res0402]
R99  10K  [res0402]
R100  10K  [res0402]
R101  10K  [res0402]
R102  100R  [res0402]
R103  100R  [res0402]
R104  100R  [res0402]
R105  100R  [res0402]
R122  DNP  [res0402]
R123  1K  [res0402]
R145  0R  [res0402]
R146  0R  [res0402]
R147  0R  [res0402]
R148  0R  [res0402]
R149  0R  [res0402]
VREF_A_M2C  TP  [TP_50]
VREF_B_M2C2  TP  [TP_50]

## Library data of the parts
3V3_UART 3V3_VDDIN 3V3_VDSS EXT_12V0 FDEC FINC FLEXIO1 FLEXIO2 GND1-GND3 GNSS_VCCOUT USB_VBUS = TP_TH
C4 C22 C25 C30 C62 C63 = C_4.7uF_CER_16V_0402
C3 C6 C9 C11 C13 C14 C19 C23 C24 C26-C28 C32 C33 C36-C42 C46-C49 C51 C53-C61 C64 C65 C67 C68 C74 C76 = C_0.1uF_25V_Cer-0402
C5 C10 C12 C18 C21 C34 C43 C50 C52 C66 C69 C71 C72 C75 C77 C79 C82 C83 C85 C88 C91 C96-C100 = C_10uF_16V_Cer_0603
C78 C80 C81 C84 C86 C87 C89 C90 C92-C95 = C_1uF_10V_Cer-0402
D6 D7 = DIODE_TVS_3.3V_0201: TVS DIODE 3.3VWM 13VC 0402C; Manufacturer: Comchip Technology; TEMP: -55°C ~ 125°C
DS4-DS12 = LED_RED_0603
FB3-FB5 FB9 FB10 FB12-FB28 = FB__220E_0603
J7 J8 J10 = CONN_SMA_TH_ST
J13 = CONN_HEADER_3POS_2.54MM_ST
J14 = CONN_SHUNT_2POS_2.54MM
Q2-Q5 = PNP_BCE_0: TRANS PNP 45V 500MA TO236AB; Assy_OPT: P; Component Type: Transistor; MSL: 1; Manufacturer: Nexperia USA Inc.; Manufacturer Part No: BC807-40,235
R2 R6 R8 R10 R16 R23 R24 R26 R30 R31 R34 R37 R39-R42 R44 R54 R55 R59 R63 R64 R66 R70 R73 R74 R76-R78 R88 R116 R129 R134 R145-R149 = R_0R_0402_0.063W
R14 R15 R17 R19 R25 R27 R35 R43 R48 R51 R53 R56 R57 R65 R89 R106-R111 R122 R130 R135-R142 = R_4.7K_0402_1%_0.1W
R46 R47 R49 R50 R60 R62 = R_49.9R_0603_1%_0.125W: RES 49.9 OHM 1% 1/10W 0402; Manufacturer Part No: RK73H1ERTTP49R9F
R52 R58 R117 R143 = R_33R_0402_1%_0.1W
R67 R80-R87 R112 R113 R120 = R_470R_0402_1%_0.063W
R79 R90 R92 R94 R96 R98-R101 R115 R118 R119 R131 R132 = R_10K_0402_1%_1_16W
R9 R20 R36 R61 R91 R93 R95 R97 R102-R105 R114 = R_100R_0402_1%_0.1W
U8 = IC_SiT95147_0
BT1 = BAT_CR2032_3.3V
C2 = C_47pF_50V_CER_0402
C70 = C_0.1uF_25V_Cer-0402: SMD AUTO C0G, CERAMIC, 10NF, 5%,; Manufacturer: KEMET; Manufacturer Part No: C0603C103J4GACAUTO; VOLTAGE RATED: 16V
C73 = C_1uF_25V_Cer_0603_Au
D1 = DIODE_TVS_40V_0402
D2 = DIODE_TVS_17V_SOT23-6
D3 = DIODE_SCHOTTKY_30V_200mA_SOT-23
D5 D8 D9 = DIODE_TVS_7V_0402
DPLL_RST# GNSS_RESET# GNSS_VBKP VREF_A_M2C VREF_B_M2C2 = TP_SMD
FB1 = FB__30E_0603
FB2 = FB__75E_0402
FB7 FB8 = FB__1K_0603
1V8_VCC 3V3_1 3V3_2 3V3_4 3V3_VCC 5V0_VCC 12V0_VIN GNSS_EXTINT0 GNSS_EXTINT1 = TP_SMD: Component Type: Test Point
J2 = CONN_USB_MINI_B_TH_ST_1734753-1
J3 = CONN_SMA_SMD_ST
J4 = BATT_HOLDER_20MM_SMD
J9 J11 = CONN_HEADER_4POS_2.54MM_ST
L1 = IND_27nH_350mA_0402: FIXED IND 27NH 350MA 460MOHM SMD; Manufacturer Part No: LQG15HS27NJ02D
R4 R5 R7 R13 R21 R22 R32 R69 R126-R128 = R_0R_0603_0.1W
R11 R12 = R_27R_0402_0.1W
R18 R38 R150 R151 = R_330R_0402_1%_0.1W
R28 R33 = R_51R_0402_1%_0.1W
R124 R125 = R_10R_0603_5%_0.1W_Au
SW1 SW2 = SWITCH_TACTILE_SPST-NO_0.05A_12
U1 = GNSS_Module_LEA-M8T-0
U4 U5 U9 = IC_74LVCE1G126W5-7
J6 = CONN_RJ45_STACKED_TH
U2 = IC_MAX3032EESE+_16-SOIC
U6 = IC_MAX33076EASE+_16-SOIC
U7 = IC_SiT5711
C1 = CAP-0402: CAP CER 0.1UF 500V X7R 1210; Assy_OPT: P; Component Type: Ceremic Capacitor; MSL: 1; Manufacturer: KEMET; Manufacturer Part No: C1210C104KCRACTU; REUSE_ANNOTATE: TRUE; ROHS/NON-ROHS: ROHS; TEMP: -55°C ~ 125°C; TOLERANCE: ±10%; VOLTAGE RATED: 500V
C7 C15 = C_4.7uF_CER_25V_0603
C8 = C_10uF_25V_Cer_0805
C16 C17 C35 = C_47uF_10V_Cer_0805
C20 = C_22nF_25V_CER_0402
C29 C44 = C_2.2uF_CER_25V_0402
D4 = DIODE_SCHOTTKY_20V_3A_SMD
DS1-DS3 DS13-DS15 = LED_GREEN_0603
F1 = FUSE_500MA_0603: FUSE BOARD MNT 1.5A 32VAC 63VDC
FB11 = FB__180E_0805: FERRITE BEAD 180 OHM 0805 1LN; Assy_OPT: P; Manufacturer: Würth Elektronik; Manufacturer Part No: 74279220181
J1 = CONN_RCPT_POWER_JACK_2.10MM
J5 = SW_SPDT_28V_5A
MH1-MH6 = M_HOLE: Component Type: Mounting Hole
Q1 Q6-Q10 = TRANS_NPN_BC847C_SOT-23
R1 = R_2R_0805_1%_0.125W
R3 = R_1M_0805_1%_0.125W
R29 R45 R123 = R_1K_0402_5%_0.1W
R68 = R_16.7K_0603_0.5%_0.1W
R71 R75 = R_10K_0603_0.1%_0.1W
R72 = R_12.6K_0603_0.1%_0.1W
R121 = R_3.3K_0402_1%_0.063W
R133 = R_100K_0402_1%_0.1W: RES 100K OHM 1% 1/10W 0402; Manufacturer: Panasonic Electronic Components; Manufacturer Part No: ERJ-H2RF1003X
R144 = R_1R_1206_1%_0.75W
U3 = VR_TPSM84205EAB
VR1 = VR_MAX8869EUE50+T
VR2 = VR_MIC37303YME-TR_8-SOIC
J12 = CONN_FMC_ASP-134488-01_ST

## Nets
3V3_AUX: FB26.2 J12.D32(3P3VAUX)
3V3_OUT: FB26.1 J12.C39(3P3V1) J12.D36(3P3V2) J12.D38(3P3V4) J12.D40(3P3V3) R120.1 R122.1
12V_IN: J5.3(NO) J12.C35(12P0V1) J12.C37(12P0V2) R121.1
GND: C3.2 C4.2 C5.2 C6.2 C7.2 C8.2 C9.2 C10.2 C11.2 C12.2 C13.2 C14.2 C15.2 C16.2 C17.2 C18.2 C19.2 C20.2 C21.2 C26.2 C27.1 C29.2 C30.1 C32.1 C33.2 C34.2 C35.2 C36.1 C37.2 C38.2 C42.2 C43.2 C44.2 C47.2 C50.2 C52.2 C53.2 C60.2 C66.2 C67.2 C68.2 C69.2 C70.2 C71.2 C72.2 C73.2 C74.2 C75.2 C76.2 C77.2 C78.2 C79.2 C80.2 C81.2 C82.2 C83.2 C84.2 C85.2 C86.2 C87.2 C88.2 C89.2 C90.2 C91.2 C92.2 C93.2 C94.2 C95.2 C96.2 C97.2 C98.2 C99.2 C100.2 D2.2(GND) D4.1(Anode) D5.1 D6.1 D7.1 D8.1 D9.1 DS1.K DS3.K DS4.K DS5.K DS6.K DS7.K DS13.K DS14.K DS15.K FB2.1 GND1.1 GND2.1 GND3.1 J1.2(GND) J1.3(GND) J2.5(GND) J3.S1(Shield1) J3.S2(Shield2) J4.3(3-) J6.4L J6.4R J7.2(Shield1) J7.3(Shield2) J7.4(Shield3) J7.5(Shield4) J8.2(Shield1) J8.3(Shield2) J8.4(Shield3) J8.5(Shield4) J9.4 J10.2(Shield1) J10.3(Shield2) J10.4(Shield3) J10.5(Shield4) J12.A1(GND1) J12.A4(GND2) J12.A5(GND3) J12.A8(GND4) J12.A9(GND5) J12.A12(GND6) J12.A13(GND7) J12.A16(GND8) J12.A17(GND9) J12.A20(GND10) J12.A21(GND11) J12.A24(GND12) J12.A25(GND13) J12.A28(GND14) J12.A29(GND15) J12.A32(GND16) J12.A33(GND17) J12.A36(GND18) J12.A37(GND19) J12.A40(GND20) J12.B2(GND21) J12.B3(GND22) J12.B6(GND23) J12.B7(GND24) J12.B10(GND25) J12.B11(GND26) J12.B14(GND27) J12.B15(GND28) J12.B18(GND29) J12.B19(GND30) J12.B22(GND31) J12.B23(GND32) J12.B26(GND33) J12.B27(GND34) J12.B30(GND35) J12.B31(GND36) J12.B34(GND37) J12.B35(GND38) J12.B38(GND39) J12.B39(GND40) J12.C1(GND41) J12.C4(GND42) J12.C5(GND43) J12.C8(GND44) J12.C9(GND45) J12.C12(GND46) J12.C13(GND47) J12.C16(GND48) J12.C17(GND49) J12.C20(GND50) J12.C21(GND51) J12.C24(GND52) J12.C25(GND53) J12.C28(GND54) J12.C29(GND55) J12.C32(GND56) J12.C33(GND57) J12.C36(GND58) J12.C38(GND59) J12.C40(GND60) J12.D2(GND61) J12.D3(GND62) J12.D6(GND63) J12.D7(GND64) J12.D10(GND65) J12.D13(GND66) J12.D16(GND67) J12.D19(GND68) J12.D22(GND69) J12.D25(GND70) J12.D28(GND71) J12.D37(GND72) J12.D39(GND73) J12.E1(GND74) J12.E4(GND75) J12.E5(GND76) J12.E8(GND77) J12.E11(GND78) J12.E14(GND79) J12.E17(GND80) J12.E20(GND81) J12.E23(GND82) J12.E26(GND83) J12.E29(GND84) J12.E32(GND85) J12.E35(GND86) J12.E38(GND87) J12.E40(GND88) J12.F2(GND89) J12.F3(GND90) J12.F6(GND91) J12.F9(GND92) J12.F12(GND93) J12.F15(GND94) J12.F18(GND95) J12.F21(GND96) J12.F24(GND97) J12.F27(GND98) J12.F30(GND99) J12.F33(GND100) J12.F36(GND101) J12.F39(GND102) J12.G1(GND103) J12.G4(GND104) J12.G5(GND105) J12.G8(GND106) J12.G11(GND107) J12.G14(GND108) J12.G17(GND109) J12.G20(GND110) J12.G23(GND111) J12.G26(GND112) J12.G29(GND113) J12.G32(GND114) J12.G35(GND115) J12.G38(GND116) J12.G40(GND117) J12.H3(GND118) J12.H6(GND119) J12.H9(GND120) J12.H12(GND121) J12.H14(LA07_N) J12.H15(GND122) J12.H18(GND123) J12.H21(GND124) J12.H24(GND125) J12.H27(GND126) J12.H30(GND127) J12.H33(GND128) J12.H36(GND129) J12.H39(GND130) J12.J1(GND131) J12.J4(GND132) J12.J5(GND133) J12.J8(GND134) J12.J11(GND135) J12.J14(GND136) J12.J17(GND137) J12.J20(GND138) J12.J23(GND139) J12.J26(GND140) J12.J29(GND141) J12.J32(GND142) J12.J35(GND143) J12.J38(GND144) J12.J40(GND145) J12.K2(GND146) J12.K3(GND147) J12.K6(GND148) J12.K9(GND149) J12.K12(GND150) J12.K15(GND151) J12.K18(GND152) J12.K21(GND153) J12.K24(GND154) J12.K27(GND155) J12.K30(GND156) J12.K33(GND157) J12.K36(GND158) J12.K39(GND159) Q1.2(E) Q6.2(E) Q7.2(E) Q8.2(E) Q9.2(E) Q10.2(E) R1.1 R2.2 R15.1 R41.1 R56.1 R63.1 R71.2 R75.2 R98.2 R99.2 R100.2 R101.2 R107.1 R108.1 R110.1 R115.2 R119.2 R123.2 R126.1 R128.1 R129.1 R130.1 R134.2 R135.2 R137.2 R138.1 R139.2 R140.2 R141.1 R142.1 SW1.1 SW2.1 U1.7(GND) U1.13(GND) U1.14(GND) U1.15(GND) U1.17(GND) U2.8(GND) U3.2(Gnd) U4.3(GND) U5.3(GND) U6.8(GND) U7.5(GND) U8.65(GND_E_PAD) U9.3(GND) VR1.10(GND) VR1.17(EPAD) VR2.1(GND) VR2.9(EP)
GND_EARTH: C1.2 D1.1 FB2.2 J2.6(SHLD1) J2.7(SHLD2) J2.8(SHLD3) J6.S1 J6.S2 MH1.1 MH2.1 MH3.1 MH4.1 MH5.1 MH6.1 R3.2
VBAT: D3.2(A2) J4.1(1+) J4.2(2+) R5.1
VCC_1V8: C44.1 FB17.1 FB19.2 FB22.1 FB23.1 FB28.1 R118.1
VCC_3V3: C29.1 FB3.1 FB4.1 FB5.1 FB12.2 FB14.1 FB15.2 FB16.1 FB20.1 FB21.1 FB24.1 FB25.1 FB27.1 Q2.2(E) Q3.2(E) Q4.2(E) Q5.2(E) R14.2 R17.2 R48.2 R84.1 R85.1 R86.1 R87.1 R90.1 R92.1 R94.1 R96.1 R112.1
VCC_5V0: FB11.2 FB13.1 FB18.1 R45.1 R124.1
VDD_DPLL_1V8: C79.1 C80.1 C92.1 C96.1 FB17.2 U8.46(VDD) U8.60(VDD)
VDDIN_DPLL_3V3: 3V3_VDDIN.1 C77.1 C78.1 FB16.2 R35.1 U8.13(VDDIN)
VDDO_0B: C93.1 C97.1 FB27.2 FB28.2 U8.22(VDDO0B)
VDDO_5: C81.1 C82.1 FB22.2 FB25.2 U8.43(VDDO5)
VDDO_DPLL_1V8: C83.1 C84.1 C85.1 C86.1 C87.1 C88.1 C89.1 C90.1 C91.1 C95.1 C98.1 C99.1 FB23.2 U8.29(VDDO1) U8.33(VDDO2) U8.36(VDDO3) U8.49(VDDO6) U8.52(VDDO7) U8.57(VDDO0T)
VDDS_DPLL_3V3: 3V3_VDSS.1 C94.1 C100.1 FB24.2 R43.1 R51.1 R57.1 R65.1 R111.2 R136.1 U8.40(VDDS)
VIN_12V0: F1.2 R144.1
1PPS_IN_N: J6.3R R34.1
1PPS_IN_P: J6.6R R37.1
BUFF1_EN1&2: R14.1 R130.2 U2.4(EN1_2)
BUFF1_EN3&4: R15.2 R17.1 U2.12(EN3_4)
BUFF_OUT_EN: R48.1 U6.4(G)
BUFF_OUT_EN#: R56.2 U6.12(G#)
CLKIN_IN0_N: C62.2 C64.2 R40.1 U8.64(IN0N)
CLKIN_IN0_P: C63.2 C65.2 R50.2 U8.63(IN0P)
DPLL_1PPS_CLKOUT_BUF: R77.2 R78.1
DPLL_1PPS_CLKOUT_N: J12.G31(LA29_N) R70.2
DPLL_1PPS_CLKOUT_P: J12.G30(LA29_P) R74.2
DPLL_CLKIN_IN0_P: C63.1 C65.1 J13.2 R54.2
DPLL_CLKOUT_0TN: C41.2 J12.G3(CLK1_M2C_N)
DPLL_CLKOUT_0TP: C40.2 J12.G2(CLK1_M2C_P)
DPLL_CLKOUT_1N: C46.2 J12.C23(LA18_N_CC)
DPLL_CLKOUT_1P: C49.2 J12.C22(LA18_P_CC)
DPLL_CLKOUT_2N: C56.2 J12.B21(GBTCLK1_M2C_N)
DPLL_CLKOUT_2P: C57.2 J12.B20(GBTCLK1_M2C_P)
DPLL_CLKOUT_10MHz_N: C51.2 J12.H5(CLK0_M2C_N)
DPLL_CLKOUT_10MHz_P: C48.2 J12.H4(CLK0_M2C_P)
DPLL_CSB: J12.C26(LA27_P) R65.2 R66.1 R140.1
DPLL_FDEC: J12.D26(LA26_P) R106.1 R107.2 U8.42(FDEC)
DPLL_FINC: J12.D27(LA26_N) R108.2 R109.1 U8.48(FINC)
DPLL_FLEXIO_1: FLEXIO1.1 J12.D21(LA17_N_CC) R73.2
DPLL_FLEXIO_2: FLEXIO2.1 J12.D18(LA13_N) R76.2
DPLL_I2C_SCL: R43.2 R44.1 R117.1 R135.1
DPLL_I2C_SDA: R57.2 R58.1 R116.1 R139.1
DPLL_I2C_SPI0: J12.C18(LA14_P) R110.2 R111.1 U8.39(I2C1_SPI0)
DPLL_INTRB: J12.D14(LA09_P) R136.2 U8.12(INTRb)
DPLL_OEB: J12.D15(LA09_N) R138.2 U8.11(OE0b)
DPLL_PLL_SEL0: J12.D23(LA23_P) R141.2 U8.26(PLL_SEL0)
DPLL_PLL_SEL1: J12.D24(LA23_N) R142.2 U8.27(PLL_SEL1)
DPLL_RST: C33.1 DPLL_RST#.1 R38.2 U8.6(RSTB)
DPLL_SDO: J12.C27(LA27_N) R51.2 R52.1 R137.1
EXT_12V0: EXT_12V0.1 J1.1(+5V) J5.1(NC)
FMC_OCXO_EN: R79.2 R149.2 U7.1(OE/NC)
FMC_PG_FPGA: J12.F1(PG_M2C) R118.2 R119.1
FMC_ToD_CLK_FPGA_N: C58.2 J12.D9(LA01_N_CC)
FMC_ToD_CLK_FPGA_P: C59.2 J12.D8(LA01_P_CC)
FMC_ToD_IN: J12.D11(LA05_P) R55.1
FMC_ToD_OUT: J12.D12(LA05_N) R24.1
FMC_VADJ_3V3: J12.E39(VADJ1) J12.F40(VADJ2) J12.G39(VADJ3) J12.H40(VADJ4) R113.1
FPGA_1PPS_1_IN_N: R34.2 R36.2 U6.1(B1)
FPGA_1PPS_1_IN_P: R36.1 R37.2 U6.2(A1)
FPGA_1PPS_1_OUT_N: J6.3L R9.2 R10.2
FPGA_1PPS_1_OUT_P: J6.6L R8.2 R9.1
FPGA_CLKOUT_10MHz_N: C62.1 C64.1 J12.C11(LA06_N)
FPGA_CLKOUT_10MHz_P: J12.C10(LA06_P) J13.1 R54.1
FPGA_DPLL_RESET_N: J12.C19(LA14_N) R151.1
FPGA_FMC_GPIO_1: J11.1 J12.G6(LA00_P_CC)
FPGA_FMC_GPIO_2: J11.2 J12.G9(LA03_P)
FPGA_FMC_GPIO_3: J11.3 J12.G12(LA08_P)
FPGA_FMC_GPIO_4: J11.4 J12.G15(LA12_P)
FPGA_FMC_GPIO_5: J12.G18(LA16_P) R105.1
FPGA_FMC_GPIO_6: J12.G21(LA20_P) R104.1
FPGA_FMC_GPIO_7: J12.G24(LA22_P) R103.1
FPGA_FMC_GPIO_8: J12.G27(LA25_P) R102.1
FPGA_GNSS_RESET_N: J12.H16(LA11_P) R150.1
FPGA_PG_FMC: J12.D1(PG_C2M) R114.1
FPGA_PPS_IN: J12.D17(LA13_P) R42.1
FPGA_PPS_OUT: J12.D20(LA17_P_CC) R6.1 R88.1
FPGA_ToD_DATA_IN_N: R61.2 R64.2 U6.7(B2)
FPGA_ToD_DATA_IN_P: R59.2 R61.1 U6.6(A2)
FPGA_ToD_DATA_OUT_N: J6.7L R16.2 R20.2
FPGA_ToD_DATA_OUT_P: J6.8L R20.1 R23.2
FREQ_IN: D6.2 J7.1(Centre) R39.1
FREQ_OUT: C61.2 D7.2 J8.1(Centre)
GNSS_EXTINT0: GNSS_EXTINT0.1 J12.H19(LA15_P) R21.2
GNSS_EXTINT1: GNSS_EXTINT1.1 J12.H20(LA15_N) R4.2
GNSS_I2C_SCL: J12.H11(LA04_N) R131.2 U1.2(SCL/SPI_CLK)
GNSS_I2C_SDA: J12.H10(LA04_P) R132.2 U1.1(SDA/SPI_CS#)
GNSS_RESET_N: C9.1 GNSS_RESET#.1 R18.2 U1.10(RESET_N)
GNSS_RF_IN: C2.2 D1.2 J3.1(Centre) L1.1
GNSS_RX: FB7.1 J12.H8(LA02_N) R13.2
GNSS_TIME_PULSE_1: C28.1 R33.2
GNSS_TIME_PULSE_1_BUF: R30.1 U1.28(TIMEPULSE)
GNSS_TIME_PULSE_2: J12.H13(LA07_P) R28.2
GNSS_TIME_PULSE_2_BUF: R26.1 U1.12(TP2/SAFEBOOT_N)
GNSS_TIME_PULSE_2_DPLL: J13.3 R31.2 R39.2
GNSS_TX: FB8.1 J12.H7(LA02_P) R22.2
GNSS_USB_DM: R12.1 U1.25(USB_DM)
GNSS_USB_DP: R11.1 U1.26(USB_DP)
GNSS_V_ANT: R126.2 R127.2 U1.19(V_ANT)
GNSS_VBKP: D3.3(K) GNSS_VBKP.1 R5.2 U1.11(V_BCKP)
GNSS_VCC: C72.1 C74.1 D3.1(A1) FB3.2 FB9.1 FB10.1 R7.1 R19.1 R131.1 R132.1 U1.6(VCC)
GNSS_VCC_OUT: C71.1 C73.1 GNSS_VCCOUT.1 U1.8(VCC_OUT)
GNSS_VCCRF: C3.1 C69.1 R125.1 U1.18(VCC_RF)
GNSS_VDD_USB_3V3: C75.1 C76.1 FB5.2 U1.24(VDD_USB)
LLAb: R95.1 R145.2 U8.3(LLAb)
LLBb: R93.1 R146.2 U8.4(LLBb)
LLCb: R91.1 R147.2 U8.5(LLCb)
LLDb: R97.1 R148.2 U8.47(LLDb)
OCXO_DPLL_CLK_IN: C39.1 R60.2
SyncE_RX_Clk_FMC_N: C22.1 C23.1 J12.C15(LA10_N)
SyncE_RX_Clk_FMC_P: C24.1 C25.1 J12.C14(LA10_P)
SyncE_TX_CLK_FPGA_N: C55.2 J12.D5(GBTCLK0_M2C_N)
SyncE_TX_CLK_FPGA_P: C54.2 J12.D4(GBTCLK0_M2C_P)
ToD_CLK_IN_N: J6.7R R64.1
ToD_CLK_IN_P: J6.8R R59.1
USB_VBUS_5V0: C4.1 D2.5(VBUS) FB1.1 USB_VBUS.1
V_ANT: C66.1 C67.1 C68.1 C70.1 L1.2 R124.2 R125.2 R127.1
N03714: C24.2 C25.2 R46.2 U8.14(IN2P)
N03742: C22.2 C23.2 R47.1 U8.15(IN2N)
N04040: C39.2 R62.1 R63.2 U8.61(IN3P)
N04088: C36.2 R62.2 U8.62(IN3N)
N04826: C28.2 R41.2 R49.1 U8.1(IN1P)
N04874: C27.2 R49.2 U8.2(IN1N)
N05220: C30.2 R46.1 R47.2
N05956: C49.1 U8.31(OUT1P)
N05960: C46.1 U8.30(OUT1N)
N09627: C60.1 U8.44(OUT5N)
N10203: C61.1 U8.45(OUT5P)
N11658: R58.2 U8.18(SDAIO)
N11816: R52.2 U8.17(SDO)
N18544: C57.1 U8.35(OUT2P)
N18564: C56.1 U8.34(OUT2N)
N18670: C59.1 U8.38(OUT3P)
N18690: C58.1 U8.37(OUT3N)
N18760: C54.1 U8.51(OUT6P)
N18780: C55.1 U8.50(OUT6N)
N18849: C48.1 U8.54(OUT7P)
N18869: C51.1 U8.53(OUT7N)
N18938: R74.1 R77.1 U8.24(OPUT0BP)
N18958: R70.1 U8.23(OUT0BN)
N19027: C40.1 U8.59(OUT0TP)
N19047: C41.1 U8.58(OUT0TN)
N16629485: Q2.1(B) R90.2 R91.2
N16634516: Q4.1(B) R94.2 R95.2
N16634528: Q4.3(C) R82.1
N16634879: Q3.1(B) R92.2 R93.2
N16634891: Q3.3(C) R81.1
N16640151: Q5.1(B) R96.2 R97.2
N16651096: 3V3_4.1 C47.1 C50.1 FB21.2 R79.1 U7.2(NF) U7.3(NF) U7.4(NF) U7.8(NF) U7.9(NF) U7.10(VDD)
N16655131: R60.1 U7.6(CLK)
N16696051: R7.2 R128.2 U1.5(D_SEL)
N16697865: D5.2 R18.1 R19.2 R150.2 SW1.2
N16718433: R21.1 U1.27(EXTINT0)
N16718470: R4.1 U1.20(EXTINT1)
N16768181: J12.K1(VREF_B_M2C2) VREF_B_M2C2.1
N16814322: R44.2 U8.16(SCLK)
N16820654: FB1.2 J2.1(VBUS)
N16820665: D2.4(IO2) J2.2(D_N)
N16820678: D2.6(IO1) J2.3(D_P)
N16820682: J2.4(ID) R2.1
N16820952: D2.1(IO1) R11.2
N16820965: D2.3(IO2) R12.2
N16845153: 3V3_1.1 C5.1 C6.1 FB4.2 U2.16(VCC)
N16845665: R6.2 U2.1(DI1)
N16845700: R24.2 U2.7(DI2)
N16845738: R8.1 U2.2(D01+)
N16845741: R10.1 U2.3(D01-)
N16845766: R23.1 U2.6(D02+)
N16845772: R16.1 U2.5(D02-)
N16854739: 3V3_2.1 C21.1 C26.1 FB14.2 U6.16(VCC)
N16856469: R42.2 U6.3(Y1)
N16856489: R55.2 U6.5(Y2)
N16859835: J12.H1(VREF_A_M2C) VREF_A_M2C.1
N16859837: J12.H2(PRSNT_M2C_L) R122.2 R123.1
N16865896: J6.5R R134.1
N16877799: R76.1 U8.55(FLEXIO14)
N16877802: R73.1 U8.56(FLEXIO15)
N16877935: J12.C30(SCL) R117.2
N16893531: C18.1 C19.1 FB13.2 R32.1 VR1.2(IN) VR1.3(IN) VR1.4(IN) VR1.5(IN)
N16893545: 1V8_VCC.1 C42.1 C43.1 FB19.1 R53.1 R72.1 R133.1 VR1.12(OUT) VR1.13(OUT) VR1.14(OUT) VR1.15(OUT)
N16893667: R71.1 R72.2 VR1.11(SET)
N16893671: R133.2 VR1.6(RST#)
N16893693: R32.2 VR1.7(SHDN#)
N16893707: C20.1 VR1.8(SS)
N16912986: C52.1 C53.1 FB20.2 R89.1 U9.5(VCC)
N16915219: R89.2 U9.1(OE)
N16915924: D9.2 J10.1(Centre) R143.2
N16916680: R143.1 U9.4(Y)
N16916839: 3V3_UART.1 FB12.1 J9.1
N16916898: J9.2 R22.1
N16916902: J9.3 R13.1
N16935425: DS12.A R112.2
N16935439: DS12.K Q10.3(C)
N16935462: Q10.1(B) R114.2 R115.1
N16941254: DS11.K Q9.3(C)
N16941276: Q9.1(B) R101.1 R105.2
N16941577: DS10.K Q8.3(C)
N16941599: Q8.1(B) R100.1 R104.2
N16941903: DS9.K Q7.3(C)
N16941925: Q7.1(B) R99.1 R103.2
N16942241: DS8.K Q6.3(C)
N16942263: Q6.1(B) R98.1 R102.2
N16943006: R66.2 U8.19(CSB)
N16943038: J12.C31(SDA) R116.2
N16943545: R78.2 R88.2 U9.2(A)
N16956953: C10.1 C11.1 FB9.2 R25.1 U4.5(VCC)
N16957025: R28.1 R31.1 U4.4(Y)
N16957049: R25.2 U4.1(OE)
N16957103: R26.2 U4.2(A)
N16958675: C12.1 C13.1 FB10.2 R27.1 U5.5(VCC)
N16958756: R27.2 U5.1(OE)
N16958772: R30.2 U5.2(A)
N16959377: R33.1 U5.4(Y)
N16976206: FB8.2 U1.3(TXD/SPI_MISO)
N16976262: FB7.2 U1.4(RXD/SPI_MOSI)
N16976717: J6.5L R129.2
N17028907: 12V0_VIN.1 C7.1 C8.1 R144.2 U3.1(Vin)
N17028917: 5V0_VCC.1 C14.1 C15.1 C16.1 C17.1 FB11.1 R29.1 U3.3(Vout)
N17029000: DS1.A R29.2
N17029235: D4.2(Cathode) F1.1 J5.2(COM)
N17059741: C34.1 C37.1 FB18.2 R69.1 VR2.3(VIN) VR2.4(VIN)
N17060506: R69.2 VR2.2(EN)
N17060596: 3V3_VCC.1 C35.1 C38.1 FB15.1 R67.1 R68.1 VR2.5(VOUT) VR2.6(VOUT)
N17066122: R68.2 R75.1 VR2.7(ADJ)
N17088502: DS2.A R45.2
N17088504: Q1.1(B) R53.2
N17088514: DS2.K Q1.3(C)
N17132603: C32.2 R40.2 R50.1
N17161015: FDEC.1 R106.2
N17161016: FINC.1 R109.2
N17172835: D8.2 R35.2 R38.1 R151.2 SW2.2
N17178888: C1.1 R1.2 R3.1
N17181808: C2.1 U1.16(RF_IN)
N17224572: DS6.A R82.2
N17227316: DS5.A R81.2
N17228504: DS7.A R83.2
N17357679: DS4.A R80.2
N17357680: Q5.3(C) R83.1
N17357681: Q2.3(C) R80.1
N17358402: DS15.A R121.2
N17358403: DS14.A R120.2
N17358404: DS3.A R67.2
N17358405: DS13.A R113.2
N17363834: J12.G33(LA31_P) R145.1
N17363854: J12.G34(LA31_N) R146.1
N17363874: J12.G36(LA33_P) R147.1
N17363894: J12.G37(LA33_N) R148.1
N17367094: J12.G28(LA25_N) R149.1
N17418314: DS9.A R85.2
N17418315: DS11.A R87.2
N17418316: DS10.A R86.2
N17418317: DS8.A R84.2

Not connected (* = marked no-connect by the designer): J6 1L 1R 2L 2R; J12 A2(DP1_M2C_P) A3(DP1_M2C_N) A6(DP2_M2C_P) A7(DP2_M2C_N) A10(DP3_M2C_P) A11(DP3_M2C_N) A14(DP4_M2C_P) A15(DP4_M2C_N) A18(DP5_M2C_P) A19(DP5_M2C_N) A22(DP1_C2M_P) A23(DP1_C2M_N) A26(DP2_C2M_P) A27(DP2_C2M_N) A30(DP3_C2M_P) A31(DP3_C2M_N) A34(DP4_C2M_P) A35(DP4_C2M_N) A38(DP5_C2M_P) A39(DP5_C2M_N) B1(RES1)* B4(DP9_M2C_P) B5(DP9_M2C_N) B8(DP8_M2C_P) B9(DP8_M2C_N) B12(DP7_M2C_P) B13(DP7_M2C_N) B16(DP6_M2C_P) B17(DP6_M2C_N) B24(DP9_C2M_P) B25(DP9_C2M_N) B28(DP8_C2M_P) B29(DP8_C2M_N) B32(DP7_C2M_P) B33(DP7_C2M_N) B36(DP6_C2M_P) B37(DP6_C2M_N) B40(RES0)* C2(DP0_C2M_P) C3(DP0_C2M_N) C6(DP0_M2C_P) C7(DP0_M2C_N) C34(GA0) D29(TCK) D30(TDI) D31(TDO) D33(TMS) D34(TRST_L) D35(GA1) E2(HA01_P_CC) E3(HA01_N_CC) E6(HA05_P) E7(HA05_N) E9(HA09_P) E10(HA09_N) E12(HA13_P) E13(HA13_N) E15(HA16_P) E16(HA16_N) E18(HA20_P) E19(HA20_N) E21(HB03_P) E22(HB03_N) E24(HB05_P) E25(HB05_N) E27(HB09_P) E28(HB09_N) E30(HB13_P) E31(HB13_N) E33(HB19_P) E34(HB19_N) E36(HB21_P) E37(HB21_N) F4(HA00_P_CC) F5(HA00_N_CC) F7(HA04_P) F8(HA04_N) F10(HA08_P) F11(HA08_N) F13(HA12_P) F14(HA12_N) F16(HA15_P) F17(HA15_N) F19(HA19_P) F20(HA19_N) F22(HB02_P) F23(HB02_N) F25(HB04_P) F26(HB04_N) F28(HB08_P) F29(HB08_N) F31(HB12_P) F32(HB12_N) F34(HB16_P) F35(HB16_N) F37(HB20_P) F38(HB20_N) G7(LA00_N_CC) G10(LA03_N) G13(LA08_N) G16(LA12_N) G19(LA16_N) G22(LA20_N) G25(LA22_N) H17(LA11_N) H22(LA19_P) H23(LA19_N) H25(LA21_P) H26(LA21_N) H28(LA24_P) H29(LA24_N) H31(LA28_P) H32(LA28_N) H34(LA30_P) H35(LA30_N) H37(LA32_P) H38(LA32_N) J2(CLK3_M2C_P) J3(CLK3_M2C_N) J6(HA03_P) J7(HA03_N) J9(HA07_P) J10(HA07_N) J12(HA11_P) J13(HA11_N) J15(HA14_P) J16(HA14_N) J18(HA18_P) J19(HA18_N) J21(HA22_P) J22(HA22_N) J24(HB01_P) J25(HB01_N) J27(HB07_P) J28(HB07_N) J30(HB11_P) J31(HB11_N) J33(HB15_P) J34(HB15_N) J36(HB18_P) J37(HB18_N) J39(VIO_B_M2C1) K4(CLK2_M2C_P) K5(CLK2_M2C_N) K7(HA02_P) K8(HA02_N) K10(HA06_P) K11(HA06_N) K13(HA10_P) K14(HA10_N) K16(HA17_P_CC) K17(HA17_N_CC) K19(HA21_P) K20(HA21_N) K22(HA23_P) K23(HA23_N) K25(HB00_P_CC) K26(HB00_N_CC) K28(HB06_P_CC) K29(HB06_N_CC) K31(HB10_P) K32(HB10_N) K34(HB14_P) K35(HB14_N) K37(HB17_P_CC) K38(HB17_N_CC) K40(VIO_B_M2C3); U1 9(RESERVED)* 21(RESERVED)* 22(RESERVED)* 23(RESERVED)*; U2 9(DI3)* 10(D03+)* 11(D03-)* 13(D04-)* 14(Do4+)* 15(DI4)*; U6 9(B3)* 10(A3)* 11(Y3)* 13(Y4)* 14(A4)* 15(B4)*; U7 7(RSVD)*; U8 7(NC)* 8(NC)* 9(NC)* 10(NC)* 20(NC)* 21(NC)* 25(NC)* 28(NC)* 32(NC)* 41(NC)*; VR1 1(NC)* 9(NC)* 16(NC)*; VR2 8(FLG)*

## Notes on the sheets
sheet 1
- PTP_DAUGHTER_BOARD
- REVISION 2.1
sheet 2
- FMC Connector
- GPIO Signals
- Text: GPIO1-4
- Text: GPIO5
- Text: GPIO6
- Text: GPIO7
- Text: GPIO8
sheet 3
- OCXO
- 1PPS & ToD Data Test Input & Output
- RS422 Driver
- RS422 Receiver
- Stacked RJ48 Connector
sheet 4
- FMC Connector
- 1PPS_Out Buffer
sheet 7
- 12V POWER JACK
- 12V SELECTION SWITCH
- 12.0V to 5.0V
- 5.0V to 3.3V
- 5.0V to 1.8V
- Carrier Card Power Good
- FMC Card Power Good
- Carrier Card 12.0V & 3.3V PWR Indication  Leds
sheet 8
- GNSS
- Place near J2
- 1PPS Signal Buffer
- 1PPS Signal Buffer
- Time Pulse2 - Route as
  separate trace to DPLL &
  FMC Connector
sheet 9
- DPLL
- Default Jumper Position: 1-2-->FPGA_Clkout_10MHZ
  Single Ended) is connected
  To connect external frequency input, change
  jumper position to 2-3
  To connect differential FPGA_Clkout_10MHz input,
  place jumper on 1-2, mount C64-0.1uF;
  C62,C63,C32-4.7uF;R40-49.9Ohm
- Place the test Points as pairs
  (DPLL_FDEC_FDEC & DPLL_FINC_FINC,
  with 2.54mm pitch
- Text: LLAb
- Text: LLBb
- Text: LLCb
- Text: LLDb
sheet 10
- Index
- Revision Record
- S No
- Title
- Page No
- Revision
- Date
- Description of Change
- Author
- Block Diagram
- 01
- 03
- V1.0
- May 1,2022
- Initial Design
- 02
- Power Architecture
- 04
- V2.0
- Jan 25, 2023
- Added DPLL status signals to
  FMC connector
  U6 GND pin connected
  FB6 replaced with
  1Ohm resistor
- 03
- DPLL
- 05
- 04
- GNSS
- 06
- V2.1
- Jul 25, 2023
- Added Jumper on DPLL INO to
  change the input between
  external frequency and 10MHz
  input from FPGA
  Renamed DPLL Output and Inout
  signals as per  application
  Reconnected GNSS Reset signal
  form FPGA to GNSS Reset switch
  Added DPLL Loss of Lock and
  FLEXIO signals to FMC
  connector
- 05
- OCXO_RJ48
- 07
- 06
- Power_3V3_1V8
- 08
- 07
- FMC_Connector_1
- 09
- 08
- FMC_Connector_2
- 10
